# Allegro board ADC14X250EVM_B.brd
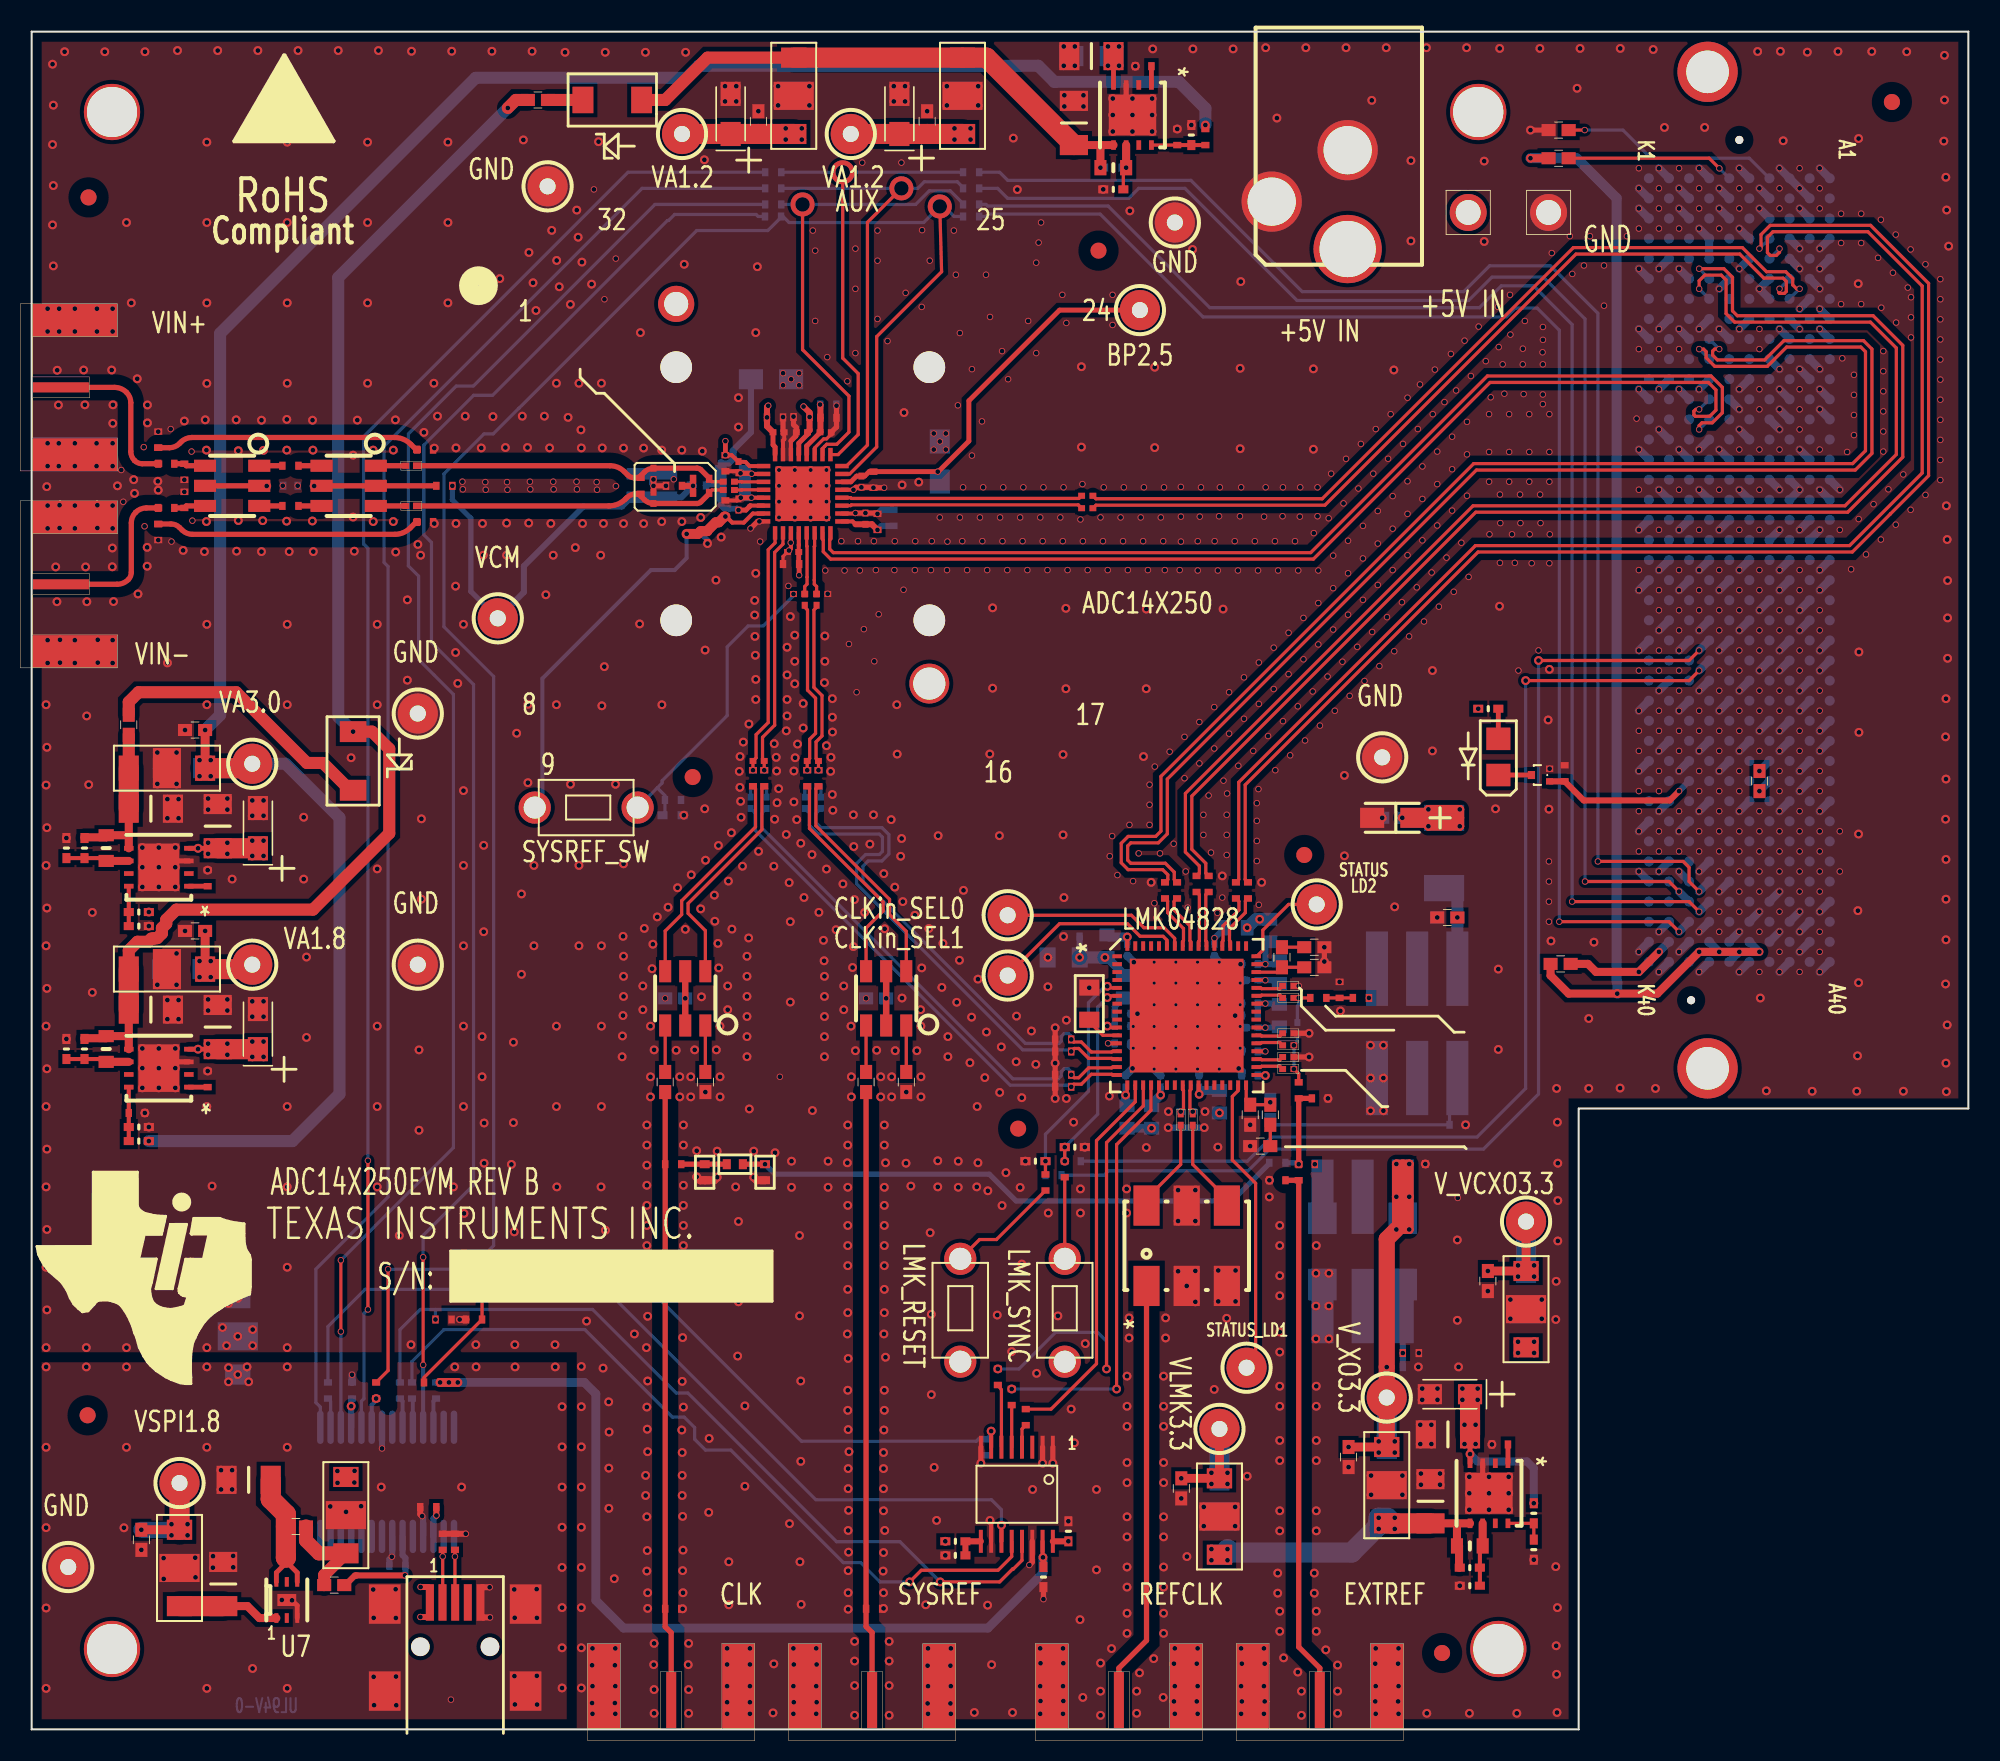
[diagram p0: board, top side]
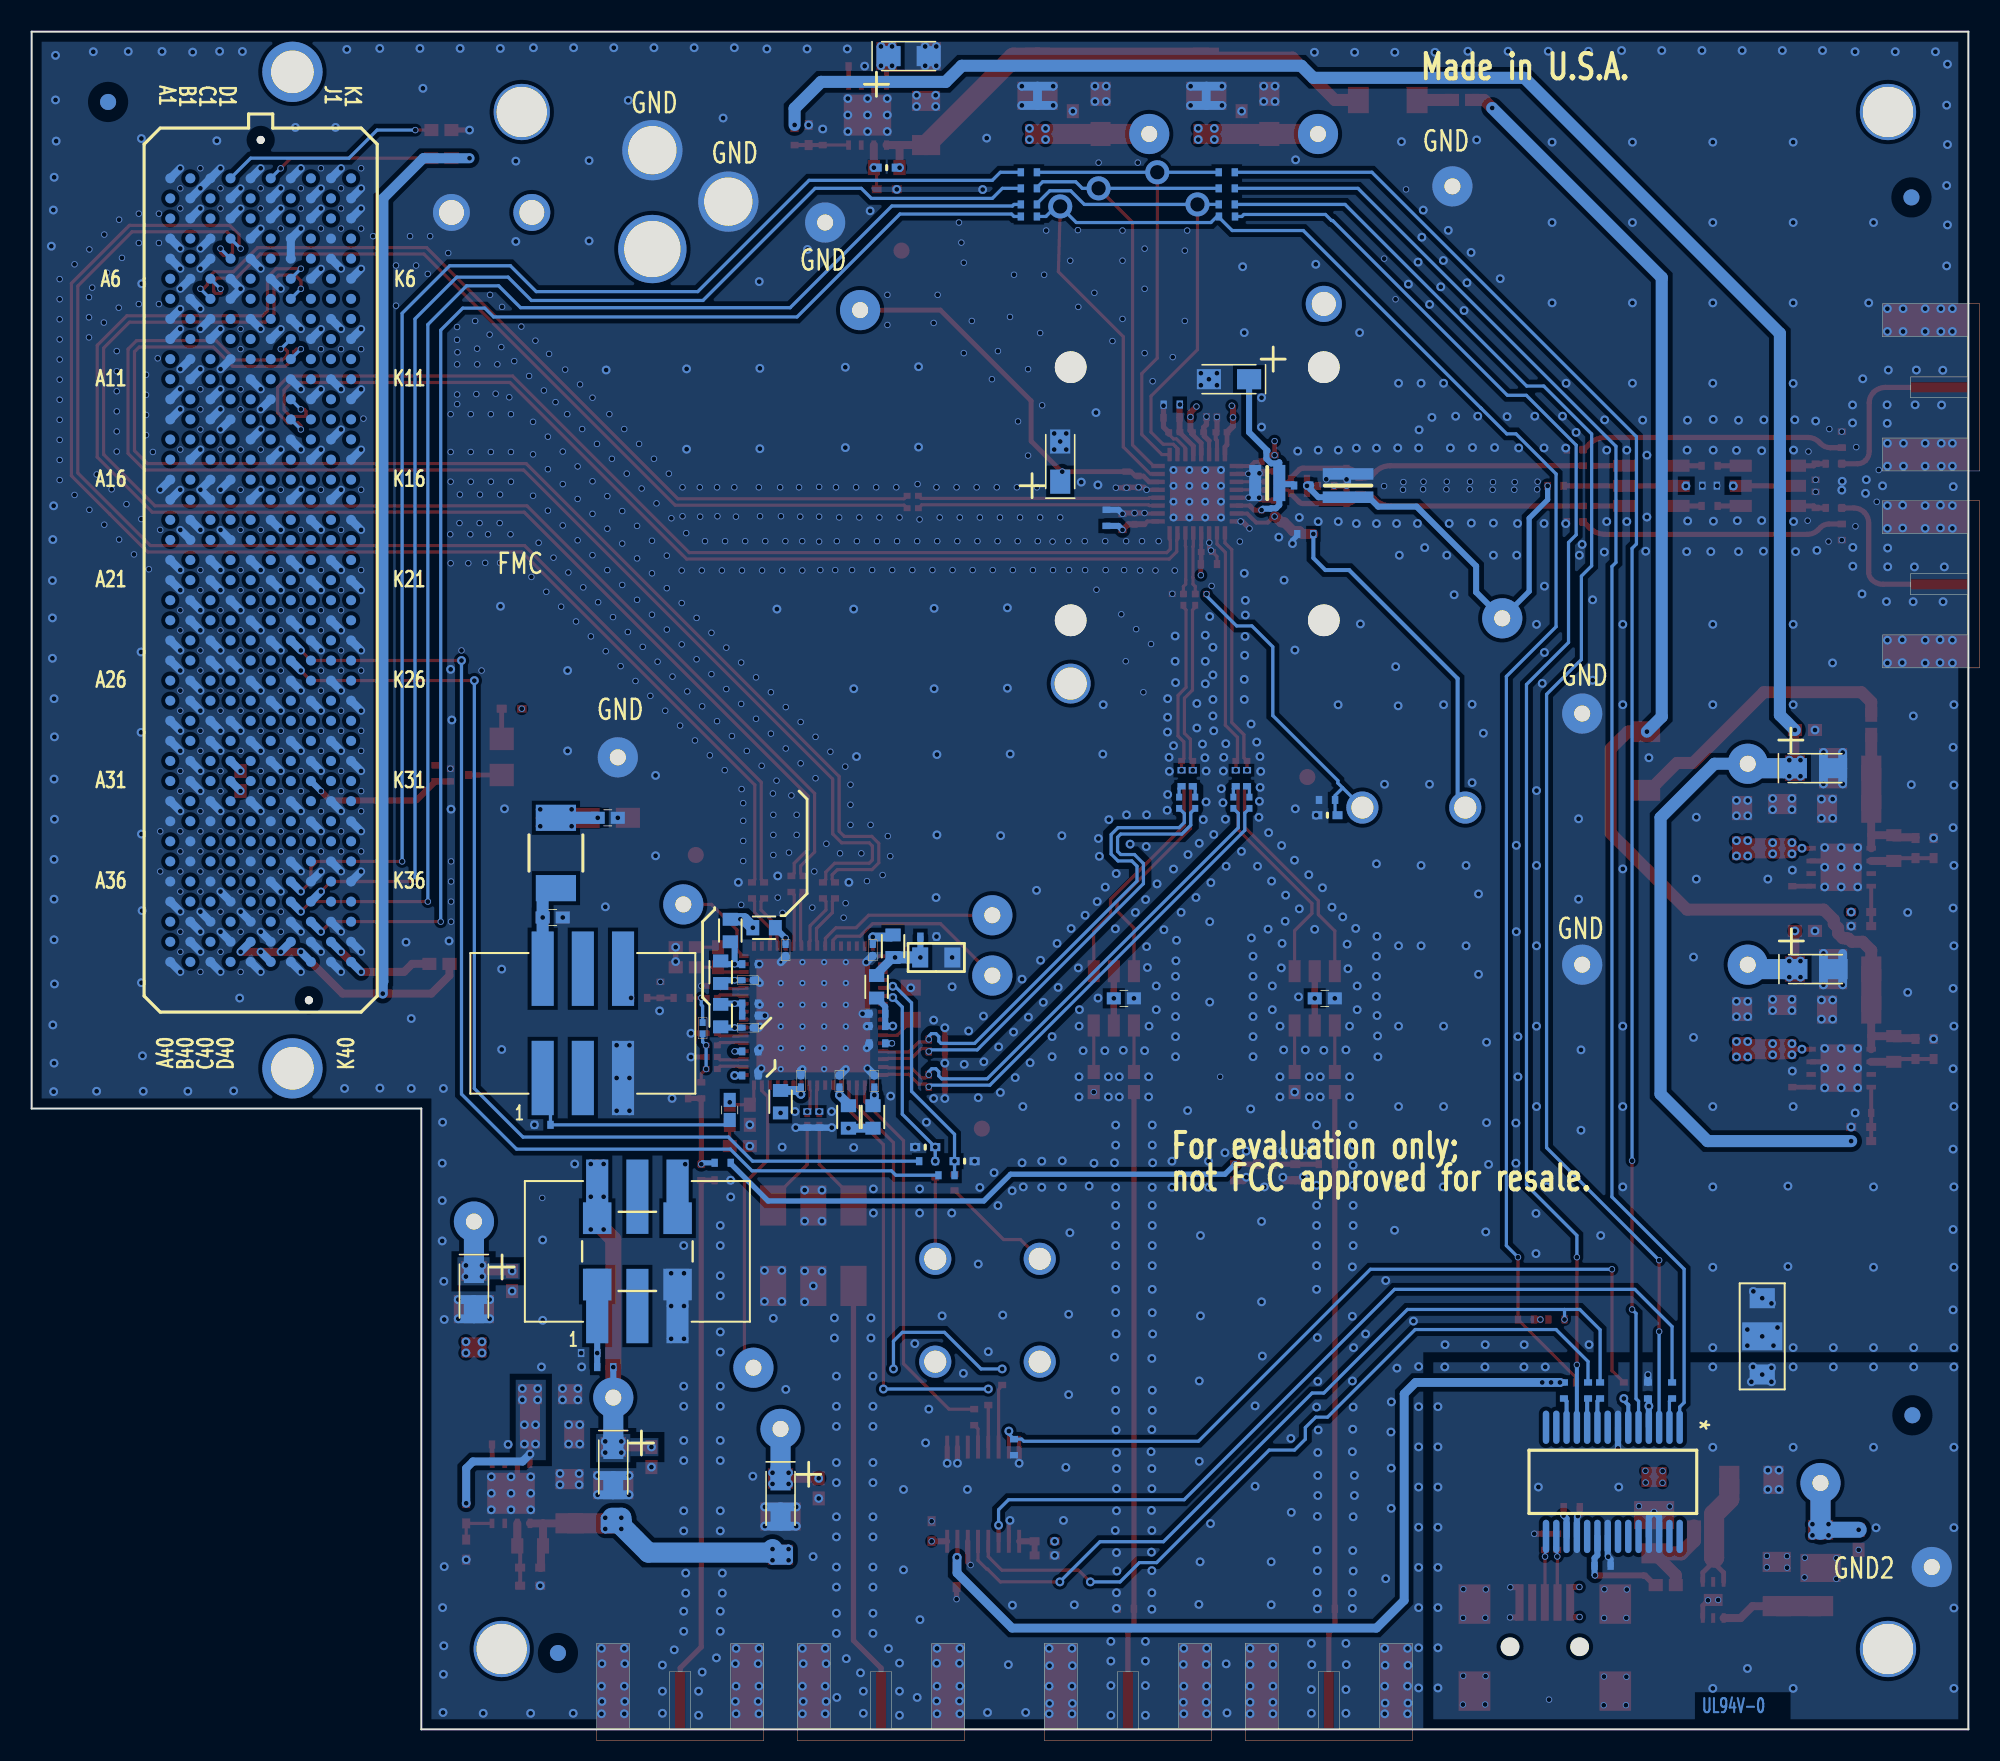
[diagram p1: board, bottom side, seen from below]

Outline 122.42 x 107.31 mm; copper layers: TOP, L2_GND, L3_POWER, L4_GND, L5_GND, BOTTOM. Coordinates in mm from the lower left corner of the outline.
Outline path: 0,107.31 0,0 97.79,0 97.79,39.24 122.42,39.24 122.42,107.31 0,107.31

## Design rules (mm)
net group CLKIN: nets CLKIN+ CLKIN-
net group CLKOUT2: nets CLKOUT2+ CLKOUT2-
net group CLKOUT3: nets CLKOUT3+ CLKOUT3-
net group CLKOUT4: nets CLKOUT4+ CLKOUT4-
net group CLKOUT8: nets CLKOUT8+ CLKOUT8-
net group CLKOUT10: nets CLKOUT10+ CLKOUT10-
net group CLKOUT11: nets CLKOUT11+ CLKOUT11-
net group DIFFPAIR3: nets SYNCB+ SYNCB-
net group DIFFPAIR5: nets N17242573 N17242594
net group DIFFPAIR6: nets SO+ SO-
net group EXT_CLK: nets EXT_CLK+ EXT_CLK-
net group EXT_SYSREF: nets EXT_SYSREF+ EXT_SYSREF-
net group FMC_FPGA_DEVCLKA: nets FMC_FPGA_DEVCLKA+ FMC_FPGA_DEVCLKA-
net group FMC_FPGA_DEVCLKB: nets FMC_FPGA_DEVCLKB+ FMC_FPGA_DEVCLKB-
net group FMC_FPGA_SYSREF: nets FMC_FPGA_SYSREF+ FMC_FPGA_SYSREF-
net group LMK_ADC_DEVCLK: nets LMK_ADC_DEVCLK+ LMK_ADC_DEVCLK-
net group LMK_ADC_SYSREF: nets LMK_ADC_SYSREF+ LMK_ADC_SYSREF-
net group REFCLK: nets REFCLK+ REFCLK-
net group SSREF: nets SSYSREF+ SSYSREF-
net group SYSREF: nets SYSREF+ SYSREF-
net group VIN: nets VIN+ VIN-

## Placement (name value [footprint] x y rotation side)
C1  0.1u  [C0402_NO_SS]  43.85 80.04 270 top
C2  0.01u  [0201]  44.68 79.78 270 top
C3  10u  [C0402_NO_SS]  41.91 75.56 180 bottom
C4  10u  [C0402_NO_SS]  54.48 76.58 270 bottom
C5  10u  [C0402_NO_SS]  50.36 83.74 180 bottom
C7  0.1u  [C0402_NO_SS]  46.99 82.93 0 top
C8  0.01u  [0201]  47.22 81.99 0 top
C9  0.1u  [C0402_NO_SS]  50.37 82.91 0 top
C10  0.01u  [0201]  50.19 81.99 0 top
C11  0.1u  [C0402_NO_SS]  43.85 77.17 90 top
C12  0.01u  [0201]  42.71 75.39 270 top
C13  0.01u  [0201]  48.69 81.99 180 top
C14  A/R  [C0402_NO_SS]  17.32 78.61 180 bottom
C15  0.1u  [C0402_NO_SS]  48.67 82.96 180 top
C16  A/R  [C0402_NO_SS]  15.39 78.61 0 bottom
C17  A/R  [0201]  39.31 79.37 270 top
C18  0.1u  [C0402_NO_SS]  48.01 73.66 180 top
C19  A/R  [C0402_NO_SS]  38.49 78.61 270 top
C20  0.01u  [C0402_NO_SS]  16.36 79.88 0 top
C21  0.01u  [C0402_NO_SS]  16.36 77.34 0 top
C22  1u  [C0402_NO_SS]  40.6 78.61 180 top
C23  A/R  [0201]  39.31 77.84 90 top
C24  0.01u  [0201]  48.13 74.42 180 top
C25  0.1u  [0201]  44.68 77.43 90 top
C26  1u  [0508]  44.32 78.78 0 bottom
C27  10u  [CAP_A-CASE]  46.74 85.34 0 bottom
C28  0.1u  [0603]  40.05 40.92 90 top
C29  0.1u  [0603]  42.59 40.92 90 top
C31  0.1u  [0603]  40.68 46.21 180 bottom
C32  10u  [0612]  39.21 78.62 90 bottom
C34  0.1u  [C0402_NO_SS]  53.47 76.33 90 top
C35  0.01u  [0201]  52.7 76.53 90 top
C36  0.01u  [0201]  66.73 77.98 0 top
C37  0.01u  [0201]  66.73 77.19 0 top
C43  0.01u  [0201]  52.45 78.87 270 top
C44  0.1u  [C0402_NO_SS]  53.21 78.99 270 top
C45  10u  [CAP_A-CASE]  57.4 80.14 90 bottom
C47  0.1u  [C0402_NO_SS]  68.97 43.36 0 bottom
C48  10u  [0805]  66.85 45.87 90 top
C51  0.1u  [C0402_NO_SS]  81.33 46.23 0 top
C53  0.1u  [0603]  52.75 40.92 90 top
C55  0.1u  [0603]  55.29 40.92 90 top
C56  0.1u  [0603]  53.38 46.21 180 bottom
C57  A/R  [C0402_NO_SS]  87.18 23.79 0 bottom
C58  A/R  [C0402_NO_SS]  87.59 35.74 0 top
C59  0.1u  [0603]  86 57.62 180 bottom
C60  10u  [SMD_SIZE3216]  86 57.62 180 top
C61  0.1u  [C0402_NO_SS]  68.97 44.46 0 bottom
C63  A/R  [C0402_NO_SS]  90.13 38.21 0 bottom
C64  100p  [0603]  89.48 51.32 180 bottom
C65  0.1u  [0603]  89.48 51.32 180 top
C66  0.1u  [0201]  79.43 47 180 top
C67  A/R  [0201]  79.43 46.23 180 top
C68  0.1u  [0201]  48.87 58.57 90 bottom
C69  0.1u  [0201]  49.89 58.57 90 bottom
C70  0.1u  [0201]  45.44 58.57 90 bottom
C71  0.1u  [0201]  46.46 58.57 90 bottom
C80  0.1u  [0201]  73.39 38.54 270 top
C81  0.1u  [0201]  72.63 38.54 270 top
C82  0.1u  [SMD_SIZE0402]  65.53 12.52 270 top
C83  0.1u  [SMD_SIZE0402]  63.96 9.63 90 top
C84  0.1u  [C0402_NO_SS]  25.07 14.05 180 top
C86  47p  [C0402_NO_SS]  26.76 11.85 90 top
C87  0.1u  [SMD_SIZE0402]  40.51 57.78 180 bottom
C92  10u  [0805]  65.24 48.79 180 bottom
C93  1u  [C0402_NO_SS]  65.74 50.11 180 bottom
C95  0.1u  [0603]  6.93 11.98 270 top
C96  10u  [SMD_SIZE1206]  13.72 15.77 180 top
C99  0.1u  [0603]  45.94 101.65 90 top
C102  10u  [SMD_SIZE1206]  12.11 9.19 90 top
C103  10u  [CAP_A-CASE]  66.99 105.77 180 bottom
C104  10u  [CAP_A-CASE]  44.18 102.12 90 top
C105  1u  [SMD_SIZE1206]  66.99 105.77 180 top
C106  0.1u  [C0402_NO_SS]  72.42 100.65 270 top
C107  2.2n  [SMD_SIZE0603]  68.37 98.72 0 top
C108  0.01u  [C0402_NO_SS]  70.27 105.13 180 top
C109  10u  [SMD_SIZE1206]  65.88 101.54 90 top
C110  0.1u  [SMD_SIZE0402]  63.45 35.92 0 top
C111  0.1u  [0603]  56.61 101.65 90 top
C112  10u  [CAP_A-CASE]  54.85 102.12 90 top
C113  0.1u  [0603]  10.33 50.47 180 top
C114  10u  [CAP_A-CASE]  14.3 44.26 90 top
C115  10u  [CAP_A-CASE]  9.66 48.06 180 bottom
C116  1u  [SMD_SIZE1206]  11.76 44.39 90 top
C117  0.1u  [SMD_SIZE0402]  65.94 36.8 180 bottom
C118  1u  [C0402_NO_SS]  68.97 45.24 0 bottom
C119  0.1u  [C0402_NO_SS]  6.65 38.96 180 top
C120  2.2n  [SMD_SIZE0603]  4.71 43.01 270 top
C121  0.01u  [C0402_NO_SS]  11.13 41.1 90 top
C122  10u  [SMD_SIZE1206]  7.54 45.5 0 top
C123  0.1u  [0603]  10.33 63.17 180 top
C125  10u  [CAP_A-CASE]  14.3 56.96 90 top
C126  47uF  [CAP_A-CASE]  9.7 60.76 180 bottom
C127  1u  [SMD_SIZE1206]  11.76 57.09 90 top
C128  0.1u  [0603]  72.67 15.23 270 top
C129  2.2n  [SMD_SIZE0603]  4.71 55.71 270 top
C131  0.01u  [C0402_NO_SS]  11.13 53.8 90 top
C132  10u  [SMD_SIZE1206]  7.54 58.2 0 top
C133  10u  [CAP_A-CASE]  75.08 14.6 270 bottom
C134  0.1u  [0603]  83.24 17.21 270 top
C136  10u  [CAP_A-CASE]  85.66 16.58 270 bottom
C137  10u  [CAP_A-CASE]  89.65 21.19 180 top
C139  1u  [SMD_SIZE1206]  89.52 18.65 180 top
C140  0.1u  [0603]  92.05 28.34 270 top
C141  1u  [C0402_NO_SS]  77 45.12 180 bottom
C142  2.2n  [SMD_SIZE0603]  90.91 11.6 0 top
C144  0.01u  [C0402_NO_SS]  92.81 18.01 180 top
C145  10u  [SMD_SIZE1206]  88.42 14.42 90 top
C146  10u  [CAP_A-CASE]  94.46 27.7 270 bottom
C152  0.1u  [0201]  69.15 40.97 90 bottom
C158  47p  [C0402_NO_SS]  25.98 11.85 90 top
C159  0.1u  [C0402_NO_SS]  80.09 40.39 90 top
C160  0.1u  [C0402_NO_SS]  77 41.33 180 bottom
C161  0.01u  [C0402_NO_SS]  23.12 10.34 180 bottom
C162  0.01u  [C0402_NO_SS]  20.25 21.42 90 bottom
C164  0.1u  [C0402_NO_SS]  77 48.37 180 bottom
C179  A/R  [0201]  49.97 71.77 0 top
C186  0.1u  [0201]  48.87 71.41 270 top
C187  0.1u  [0201]  49.62 71.41 270 top
C195  0.1u  [0201]  79.43 42.5 180 top
C196  0.1u  [0201]  79.43 41.74 180 top
C197  0.1u  [0201]  79.43 44 180 top
C198  A/R  [0201]  79.43 43.24 180 top
C199  0.1u  [C0402_NO_SS]  77 42.86 180 bottom
C200  0.1u  [0201]  71.36 40.97 90 bottom
C201  0.1u  [0201]  73.8 40.97 90 bottom
C202  0.1u  [0201]  74.76 49.25 270 bottom
C203  0.1u  [0201]  69.25 49.25 270 bottom
C204  0.1u  [C0402_NO_SS]  77 45.88 180 bottom
C205  0.1u  [0201]  77.15 47.35 180 bottom
C206  0.1u  [0201]  77.15 44.36 180 bottom
D1  DIODE,SCHOTTKY,CDBA140-G  [ZENER_DO_214AC]  20.32 61.21 90 top
D2  DIODE,SCHOTTKY,CDBA140-G  [ZENER_DO_214AC]  36.7 103 0 top
J1  CONN, JACK, PWR  [CON_RAPC722_JACK_THVT_3]  83.19 96.7 180 top
J2  CONN, SMA, JACK, 50 OHM, EDGE  [CON_SMA-EDGE]  1.84 84.83 0 top
J3  CONN, SMA, JACK, 50 OHM, EDGE  [CON_SMA-EDGE]  1.84 72.38 0 top
J4  CONN, SMA, JACK, 50 OHM, EDGE  [CON_SMA-EDGE]  40.43 1.84 90 top
J5  CONN, SMA, JACK, 50 OHM, EDGE  [CON_SMA-EDGE]  53.13 1.84 90 top
J6  CONN, SMA, JACK, 50 OHM, EDGE  [CON_SMA-EDGE]  68.73 1.84 90 top
J7  CONN, SMA, JACK, 50 OHM, EDGE  [CON_SMA-EDGE]  81.43 1.84 90 top
J8  CON, SMVT, HS, FIELD ARRAY, FMC, MALE  [CON_SMVT_40X10_SEAM_MTG]  107.94 73.28 90 bottom
J9  CONN, USB, MINI AB, R/A, SMT  [CON_SMRT_USBMNE20_F]  26.77 4.57 90 top
L3  330 OHM  [R0603]  69.01 46.94 90 bottom
L4  330 OHM  [R0603]  69.24 38.71 90 bottom
L5  330 OHM  [R0603]  78.26 50.5 90 bottom
L8  100uH, 158MA, 8 OHM  [SMD_SIZE1812R]  89.28 55.4 270 bottom
L9  330 OHM  [R0603]  70.79 38.71 90 bottom
L10  330 OHM  [R0603]  75.08 39.67 90 bottom
L11  330 OHM  [R0603]  76.12 50.67 180 bottom
L12  330 OHM  [R0603]  67.97 49.5 90 bottom
L13  330 OHM  [R0603]  78.87 45.12 270 bottom
L14  330 OHM  [R0603]  78.87 47.86 270 bottom
LF1_C1  8200p  [0603]  77.02 38.85 270 top
LF1_C2  0.39u  [0603]  78.29 38.85 270 top
LF1_R2  3.30k  [0603]  77.66 36.87 180 top
LF2_C1  27p  [0603]  81.08 48.17 0 top
LF2_C2  2700p  [0603]  79.03 48.81 90 top
LF2_R2  560  [0603]  81.08 49.44 0 top
MT1  STANDOFF, FEMALE, 4-40 X 1 1/16"  [MFG125_PLATED]  5.08 5.08 0 top
MT2  STANDOFF, FEMALE, 4-40 X 1 1/16"  [MFG125_PLATED]  92.71 5.08 0 top
MT3  STANDOFF, FEMALE, 4-40 X 1 1/16"  [MFG125_PLATED]  5.08 102.23 0 top
MT4  STANDOFF, FEMALE, 4-40 X 1 1/16"  [MFG125_PLATED]  91.44 102.23 0 top
NOREF  -  []  37.85 -41.53 0 top
NOREF#2  -  []  19.5 27.7 0 top
NOREF#3  -  []  2.79 25.7 0 top
NOREF#4  -  [unnamed#2]  67.44 93.47 0 top
NOREF#5  -  []  5.08 5.08 0 top
NOREF#6  -  [unnamed#2]  62.36 37.97 0 top
NOREF#7  -  [unnamed#2]  3.54 19.85 0 top
NOREF#8  -  []  -39.24 41.53 0 top
NOREF#9  -  []  0 0 90 top
NOREF#10  -  []  111.07 13.72 0 top
NOREF#11  -  []  5.08 5.08 90 top
NOREF#12  -  []  0 107.31 0 top
NOREF#13  -  [unnamed#2]  41.78 60.2 0 top
NOREF#14  -  []  0 0 0 top
NOREF#15  -  [unnamed#2]  117.59 102.87 0 top
NOREF#16  -  [unnamed#2]  3.6 96.84 0 top
NOREF#17  -  []  15.87 95.52 0 top
NOREF#18  -  [unnamed#2]  89.15 4.83 0 top
NOREF#19  -  []  205.23 22.35 0 top
NOREF#20  -  []  5.08 5.08 0 top
NOREF#21  -  [unnamed#2]  80.44 55.27 0 top
NOREF#22  -  []  15.91 102.61 0 top
NOREF#23  -  []  0 0 90 top
NOREF#24  -  []  35.64 39.22 180 bottom
NOREF#25  -  [unnamed#2]  3.6 96.84 180 bottom
NOREF#26  -  [unnamed#2]  117.59 102.87 180 bottom
NOREF#27  -  []  50.52 36.17 180 bottom
NOREF#28  -  [unnamed#2]  89.15 4.83 180 bottom
NOREF#29  -  [unnamed#2]  3.54 19.85 180 bottom
Q1  SSM3K37MFV,L3F  [SOT-723]  95.38 60.33 90 top
R1  0  [C0402_NO_SS]  8 81.52 90 top
R2  0  [C0402_NO_SS]  8 75.68 270 top
R3  0  [0201]  24 79.88 0 top
R4  A/R  [C0402_NO_SS]  9.65 77.72 270 top
R5  A/R  [C0402_NO_SS]  8 76.7 270 top
R6  A/R  [C0402_NO_SS]  24.36 76.83 90 top
R7  33  [C0402_NO_SS]  42.32 79.05 180 top
R8  A/R  [C0402_NO_SS]  26.09 78.61 0 top
R9  33  [C0402_NO_SS]  42.32 78.16 180 top
R10  0  [0201]  24 77.34 0 top
R11  A/R  [C0402_NO_SS]  8.51 80 0 top
R12  A/R  [C0402_NO_SS]  8 80.51 90 top
R13  A/R  [C0402_NO_SS]  24.36 80.38 270 top
R14  0  [C0402_NO_SS]  9.65 79.49 270 top
R15  0  [C0402_NO_SS]  8.51 77.21 0 top
R16  10  [C0402_NO_SS]  42.11 78.63 0 bottom
R17  75  [0402]  44.45 35.73 0 top
R18  A/R  [0201]  45.95 61.21 180 top
R19  300  [0402]  42.55 35.22 270 top
R20  300  [0402]  46.35 35.22 270 top
R21  0  [C0402_NO_SS]  40.55 35.73 180 top
R22  100  [C0402_NO_SS]  40.55 7.62 0 top
R23  100  [C0402_NO_SS]  53.25 7.62 0 top
R24  0  [0201]  44.07 78.87 0 top
R25  0  [0201]  44.07 78.34 0 top
R27  10K  [C0402_NO_SS]  60.32 17.84 90 bottom
R28  56  [SMD_SIZE0402]  92.08 64.52 0 top
R29  100  [0201]  49.38 61.21 180 top
R30  0  [0201]  80.01 44.32 270 bottom
R31  A/R  [C0402_NO_SS]  86.16 22.9 180 bottom
R32  A/R  [C0402_NO_SS]  87.18 23.79 180 top
R33  A/R  [C0402_NO_SS]  80.6 35.73 0 top
R34  200  [C0402_NO_SS]  80.09 35.22 90 top
R35  49.9  [C0402_NO_SS]  78.75 34.71 0 top
R36  200  [C0402_NO_SS]  81.43 39.88 180 top
R37  0  [0603]  78.29 39.15 270 bottom
R38  200  [C0402_NO_SS]  84.02 46.23 0 top
R39  200  [C0402_NO_SS]  82.68 46.74 270 top
R40  0  [C0402_NO_SS]  45.6 60.12 90 top
R41  0  [C0402_NO_SS]  46.31 60.12 90 top
R42  0  [0603]  96.65 48.39 0 top
R43  A/R  [C0402_NO_SS]  45.6 60.12 90 bottom
R44  0  [C0402_NO_SS]  49.02 60.12 90 top
R45  0  [C0402_NO_SS]  49.74 60.12 90 top
R46  121  [C0402_NO_SS]  65.2 42.85 0 top
R47  121  [C0402_NO_SS]  65.2 43.61 0 top
R48  121  [C0402_NO_SS]  65.2 40.62 0 top
R49  121  [C0402_NO_SS]  65.2 41.38 0 top
R50  A/R  [C0402_NO_SS]  46.31 60.12 90 bottom
R51  A/R  [C0402_NO_SS]  49.02 60.12 90 bottom
R52  0  [C0402_NO_SS]  24.87 80.89 0 top
R53  0  [C0402_NO_SS]  24.87 76.32 0 top
R54  121  [C0402_NO_SS]  73.39 38.54 90 bottom
R55  121  [C0402_NO_SS]  72.63 38.54 90 bottom
R56  2  [0603]  6.14 63.5 270 top
R57  22  [C0402_NO_SS]  62.84 19.74 90 top
R58  22  [C0402_NO_SS]  61.07 22.28 90 top
R59  22  [C0402_NO_SS]  61.95 21.01 90 top
R60  10K  [C0402_NO_SS]  25.56 21.42 90 bottom
R61  A/R  [C0402_NO_SS]  49.74 60.12 90 bottom
R62  2  [0603]  32 103 180 top
R63  1K  [SMD_SIZE0402]  68.37 97.35 180 top
R64  200  [SMD_SIZE0402]  68.37 98.72 180 bottom
R65  20K  [C0402_NO_SS]  74.19 100.65 90 top
R66  1K  [SMD_SIZE0402]  2.2 43.01 90 top
R67  806  [SMD_SIZE0402]  3.34 43.01 90 top
R68  10K  [SMD_SIZE0402]  6.77 37.19 180 top
R69  1K  [SMD_SIZE0402]  2.2 55.71 90 top
R70  22  [C0402_NO_SS]  46.88 97.41 0 bottom
R71  22  [C0402_NO_SS]  18.73 21.42 90 bottom
R72  22  [C0402_NO_SS]  46.88 96.39 0 bottom
R73  22  [C0402_NO_SS]  46.88 98.42 0 bottom
R74  22  [C0402_NO_SS]  21.78 21.42 90 top
R75  22  [C0402_NO_SS]  23.28 21.42 90 bottom
R76  22  [C0402_NO_SS]  24.04 21.42 90 bottom
R77  22  [C0402_NO_SS]  46.86 95.63 0 bottom
R78  2k  [SMD_SIZE0402]  3.34 55.71 90 top
R79  1K  [SMD_SIZE0402]  90.91 9.08 180 top
R80  2.32K  [SMD_SIZE0402]  90.91 10.22 180 top
R81  1K  [SMD_SIZE0402]  94.95 13.66 270 top
R82  A/R  [SMD_SIZE0402]  94.95 11.36 270 top
R83  10K  [C0402_NO_SS]  27.96 25.91 180 top
R84  10K  [C0402_NO_SS]  26.04 25.91 0 top
R85  A/R  [C0402_NO_SS]  25.31 21.93 0 top
R86  0  [SMD_SIZE0402]  58.39 11.89 0 top
R87  0  [SMD_SIZE0402]  58.39 11 0 top
R89  A/R  [SMD_SIZE0402]  73.3 100.78 270 top
R90  A/R  [SMD_SIZE0402]  6.77 38.07 180 top
R92  A/R  [C0402_NO_SS]  59.39 97.41 180 bottom
R93  A/R  [C0402_NO_SS]  59.39 98.42 0 bottom
R94  A/R  [C0402_NO_SS]  59.39 96.39 0 bottom
R95  A/R  [C0402_NO_SS]  59.39 95.63 180 bottom
R96  1K  [SMD_SIZE0402]  6.77 51.66 180 top
R97  A/R  [SMD_SIZE0402]  6.77 50.77 0 top
R102  10K  [C0402_NO_SS]  96.9 60.43 270 top
R110  1K  [SMD_SIZE0402]  63.45 35.92 180 bottom
R111  1K  [SMD_SIZE0402]  65.94 36.8 0 top
R112  0  [C0402_NO_SS]  64.08 34.57 90 top
R113  0  [C0402_NO_SS]  64.59 35.03 180 bottom
R114  0  [C0402_NO_SS]  65.81 35.92 180 bottom
R115  0  [C0402_NO_SS]  65.3 35.41 90 top
R116  0  [0603]  109.22 59.94 270 top
R119  A/R  [0201]  48.51 71.77 180 top
R120  10K  [C0402_NO_SS]  40.54 58.75 0 bottom
R155  10K  [0603]  96.52 101.09 180 top
R156  10K  [0603]  96.52 99.31 0 top
R157  0  [0603]  16.71 12.82 180 top
R158  0  [0603]  19.13 9.12 0 top
R160  0  [C0402_NO_SS]  71.64 53.03 90 top
R161  0  [C0402_NO_SS]  72.4 53.03 90 top
R162  0  [C0402_NO_SS]  73.63 53.44 90 top
R163  0  [C0402_NO_SS]  74.4 53.44 90 top
R164  0  [C0402_NO_SS]  76.12 53.03 90 top
R165  0  [C0402_NO_SS]  76.89 53.03 90 top
R227  0  [C0402_NO_SS]  78.74 35.81 180 bottom
SW1  SW, PUSHBUTTON, SPST-NO  [SW_RESET_PTS635]  65.3 26.49 90 top
SW2  SW, PUSHBUTTON, SPST-NO  [SW_RESET_PTS635]  58.7 26.49 90 top
SW3  SW, PUSHBUTTON, SPST-NO  [SW_RESET_PTS635]  35.05 58.27 0 top
SYNC  LED GREEN  [LED_0805]  92.71 61.47 270 top
T1  -  [MABA-007159-000000]  12.67 78.61 270 top
T2  -  [MABA-007159-000000]  20.04 78.61 270 top
T3  -  [MABA-007159-000000]  41.32 46.21 180 top
T4  -  [MABA-007159-000000]  54.02 46.21 180 top
T5  ADT2-1T-1P+  [ADT1-1WT]  73.01 30.57 90 top
TP1  BLK  [TP_THVT_100_RND_GND]  72.26 95.25 0 top
TP2  RED  [TP_THVT_100_RND]  41.11 100.85 0 top
TP3  RED  [TP_THVT_100_RND]  51.78 100.85 0 top
TP4  RED  [TP_THVT_100_RND]  13.94 48.34 0 top
TP5  RED  [TP_THVT_100_RND]  13.94 61.04 0 top
TP6  RED  [TP_THVT_100_RND]  75.08 18.99 0 top
TP7  RED  [TP_THVT_100_RND]  85.66 20.97 0 top
TP8  RED  [TP_THVT_100_RND]  94.46 32.1 0 top
TP9  BLK  [TP_THVT_100_RND_GND]  85.37 61.44 0 top
TP10  BLK  [TP_THVT_100_RND_GND]  32.61 97.54 0 top
TP11  BLK  [TP_THVT_100_RND_GND]  24.41 48.34 0 top
TP12  BLK  [TP_THVT_100_RND_GND]  24.41 64.21 0 top
TP13  BLK  [TP_THVT_100_RND_GND]  2.31 10.26 0 top
TP14  WHT  [TP_THVT_100_RND]  70.05 89.71 0 top
TP15  WHT  [TP_THVT_100_RND]  29.46 70.23 0 top
TP16  GRN  [TP_THVT_100_RND]  61.7 47.65 0 top
TP17  GRN  [TP_THVT_100_RND]  61.7 51.46 0 top
TP18  GRN  [TP_THVT_100_RND]  81.23 52.15 0 top
TP19  GRN  [TP_THVT_100_RND]  76.8 22.86 0 top
TP20  RED  [TP_THVT_100_RND]  9.35 15.57 0 top
TP21  Testloop_Red  [TESTPOINT_62DIA]  90.81 95.89 0 top
TP22  Testloop_Black  [TESTPOINT_62DIA]  95.89 95.89 0 top
U1  ADC14X250  [QFN_32_IRONWOOD_0P5MM]  48.74 78.11 0 top
U5  SN74AVC4T774  [TSSOP16_PW]  62.28 14.86 270 top
U6  -  [FT245RL]  22.47 15.65 270 bottom
U7  LP5900SD-1.8/NOPB  [SC-MKT-SDB06A_6LLP]  16.13 8.18 90 top
U8  LP3878SD-ADJ  [SC-MKT-SDC08A_LLP]  69.58 102.04 270 top
U9  LP3878SD-ADJ  [SC-MKT-SDC08A_LLP]  8.04 41.8 180 top
U10  LP3878SD-ADJ  [SC-MKT-SDC08A_LLP]  8.04 54.5 180 top
U11  LP3878SD-ADJ  [SC-MKT-SDC08A_LLP]  92.12 14.92 270 top
U13  LMK04828BISQ  [WQFN_64_360X360_0P5MM_PWRPAD]  73.01 45.12 0 top
Y1  CCHD-950-61.44  [SOIC6_100_WG272_L560]  84.13 30.21 90 bottom
Y2  CWX823-012.288M  [CWX813]  84.13 30.21 90 bottom
Y3  CVHD-950-122.88  [SOIC6_100_WG272_L560]  87.58 44.63 90 bottom
Z1  0.2uF, 2A,NFM41P  [NFM41P]  19.86 13.54 270 top
Z2  0.2uF, 2A,NFM41P  [NFM41P]  13.03 24.84 90 bottom
Z3  0.2uF, 2A,NFM41P  [NFM41P]  9.35 10.2 90 top
Z4  0.2uF, 2A,NFM41P  [NFM41P]  48.17 103.26 270 top
Z5  0.2uF, 2A,NFM41P  [NFM41P]  58.84 103.26 270 top
Z6  0.2uF, 2A,NFM41P  [NFM41P]  8.55 48.06 0 top
Z7  0.2uF, 2A,NFM41P  [NFM41P]  8.55 60.76 0 top
Z8  0.2uF, 2A,NFM41P  [NFM41P]  75.08 13.45 90 top
Z9  0.2uF, 2A,NFM41P  [NFM41P]  85.66 15.44 90 top
Z10  0.2uF, 2A,NFM41P  [NFM41P]  94.46 26.56 90 top

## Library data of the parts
C1 C2 C7-C15 C18 C20 C21 C24 C34 C35 C43 C44 C47 C48 C51 C57 C61 C63 C84 C86 C92 C106 C108 C119 C121 C131 C144 C158-C162 C164 C199 C204 = Cap_0
C3-C5 C22 C32 C93 C118 C141 = CAPACITOR NON-POL
C16 C17 C19 C23 C25 C26 C31 C56 C58 C59 C64 C65 C82 C83 C95 C96 C99 C102 C105 C109 C111 C113 C116 C122 C123 C127 C128 C132 C134 C139 C140 C145 LF1_C1 LF1_C2 LF2_C1 LF2_C2 = Capacitor_0
C27 C45 C60 C103 C104 C112 C114 C115 C125 C126 C133 C136 C137 C146 = Cap_Polar_1
C28 C29 C53 C55 = CAP_0603_0.1uF_H
C36 C37 C66-C71 C80 C81 C152 C179 C186 C187 C195-C198 C200-C203 C205 C206 = CAP_0201_0.1uF
C87 C107 C110 C117 C120 C129 C142 = Capacitor_1
D1 D2 = DIODE_SCHOTTKY
J1 = CONN JACK PWR
J2-J7 = SMA_CONN_0
J8 = CON_SMVT_40X10_SEAM
J9 = USB_MINI_AB_MNE20-5G5P10
L3-L5 L9-L14 = INDUCTOR FERRITE/SM
L8 = Inductor_0
LF1_R2 LF2_R2 R1 R2 R4-R9 R11-R16 R18 R21-R23 R27 R29 R31-R55 R57-R61 R63-R87 R89 R90 R92-R97 R102 R110-R116 R119 R120 R157 R158 R160-R165 R227 = Resistor_0
MT1-MT4 = MOUNTING_HOLE
Q1 = BSS138/SOT
R3 R10 R24 R25 = Res_0201_Zero_H
R17 = Res_0402_75
R19 R20 = Res_0402_300
R28 = Res_0402_56
R30 = Res_0402_Zero_DNI
R56 R62 = Res_0603_22.1
R155 R156 = Res_0603_10k_H
SW1-SW3 = SW PUSHBUTTON
SYNC = LED
T1-T4 = MABA-007159-000000
T5 = ADT2-1T-1P+_0
TP1 TP9-TP13 = TESTPOINT_BLK
TP2-TP8 TP20 = TESTPOINT_RED
TP14 TP15 = TESTPOINT_WHT
TP16-TP19 = TESTPOINT_GRN
TP21 TP22 = TESTLOOP_BLACK
U1 = ADC14X250_SOCKET_0
U5 = SN74AVC4T774
U6 = FT245RL
U7 = LP5900SD-??_1
U8-U11 = LP3878MR-ADJ_1
U13 = LMK04828BISQ
Y1 = CCHD-950-61.44
Y2 = CWX823-012.288M
Y3 = CVHD-950-122.88
Z1-Z10 = NFM41_0

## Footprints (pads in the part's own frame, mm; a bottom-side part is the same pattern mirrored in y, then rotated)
0201
  rect 0.432x0.381 smd: 1(-0.356,0) 2(0.356,0)
0402
  rect 0.508x0.635 smd: 1(-0.508,0) 2(0.508,0)
0508
  rect 0.762x2.286 smd: 1(-0.762,0) 2(0.762,0)
0603
  rect 0.889x0.762 smd: 1(-0.635,0) 2(0.635,0)
0612
  rect 0.725x3.2 smd: 1(-0.738,0) 2(0.738,0)
0805
  rect 1.016x1.27 smd: 1(-1.016,0) 2(1.016,0)
ADT1-1WT
  rect 2.54x1.651 smd: 1(-2.54,2.54) 2(-2.54,0) 3(-2.54,-2.54) 4(2.54,-2.54) 5(2.54,0) 6(2.54,2.54)
C0402_NO_SS
  rect 0.406x0.508 smd: 1(-0.508,0) 2(0.508,0)
CAP_A-CASE
  rect 1.524x1.27 smd: 1(-1.27,0) 2(1.27,0)
CON_RAPC722_JACK_THVT_3
  round 4.318 hole 3.556: 1(0,3.124)
  round 3.81 hole 3.048: 2(0,-3.124) 3(4.801,0.127)
CON_SMA-EDGE
  rect 3.556x0.635 smd: 1(0,0)
  rect 5.334x2.032 smd: 2(0.889,4.255) 3(0.889,-4.255) 4(0.889,-4.255) 5(0.889,4.255)
CON_SMRT_USBMNE20_F
  round 1.194 hole 1.168 unplated: (0.65,2.2) (0.65,-2.2)
  rect 2.311x0.508 smd: 1(3.45,1.6) 2(3.45,0.8) 3(3.45,0) 4(3.45,-0.8) 5(3.45,-1.6)
  rect 2.489x2.007 smd: 6(-2.15,-4.45) 7(3.35,-4.45) 8(3.35,4.45) 9(-2.15,4.45)
CON_SMVT_40X10_SEAM_MTG
  round 3.81 hole 2.692: (-31.496,-2.007) (31.496,-2.007)
  round 0.508 hole 1.27 unplated: (-27.191,-3.048) (27.191,0)
  round 0.635 smd: A1(24.765,5.715) A2(23.495,5.715) A3(22.225,5.715) A4(20.955,5.715) A5(19.685,5.715) A6(18.415,5.715) A7(17.145,5.715) A8(15.875,5.715) A9(14.605,5.715) A10(13.335,5.715) A11(12.065,5.715) A12(10.795,5.715) A13(9.525,5.715) A14(8.255,5.715) A15(6.985,5.715) A16(5.715,5.715) A17(4.445,5.715) A18(3.175,5.715) A19(1.905,5.715) A20(0.635,5.715) A21(-0.635,5.715) A22(-1.905,5.715) A23(-3.175,5.715) A24(-4.445,5.715) A25(-5.715,5.715) A26(-6.985,5.715) A27(-8.255,5.715) A28(-9.525,5.715) A29(-10.795,5.715) A30(-12.065,5.715) A31(-13.335,5.715) A32(-14.605,5.715) A33(-15.875,5.715) A34(-17.145,5.715) A35(-18.415,5.715) A36(-19.685,5.715) A37(-20.955,5.715) A38(-22.225,5.715) A39(-23.495,5.715) A40(-24.765,5.715) B1(24.765,4.445) B2(23.495,4.445) B3(22.225,4.445) B4(20.955,4.445) B5(19.685,4.445) B6(18.415,4.445) B7(17.145,4.445) B8(15.875,4.445) B9(14.605,4.445) B10(13.335,4.445) B11(12.065,4.445) B12(10.795,4.445) B13(9.525,4.445) B14(8.255,4.445) B15(6.985,4.445) B16(5.715,4.445) B17(4.445,4.445) B18(3.175,4.445) B19(1.905,4.445) B20(0.635,4.445) B21(-0.635,4.445) B22(-1.905,4.445) B23(-3.175,4.445) B24(-4.445,4.445) B25(-5.715,4.445) B26(-6.985,4.445) B27(-8.255,4.445) B28(-9.525,4.445) B29(-10.795,4.445) B30(-12.065,4.445) B31(-13.335,4.445) B32(-14.605,4.445) B33(-15.875,4.445) B34(-17.145,4.445) B35(-18.415,4.445) B36(-19.685,4.445) B37(-20.955,4.445) B38(-22.225,4.445) B39(-23.495,4.445) B40(-24.765,4.445) C1(24.765,3.175) C2(23.495,3.175) C3(22.225,3.175) C4(20.955,3.175) C5(19.685,3.175) C6(18.415,3.175) C7(17.145,3.175) C8(15.875,3.175) C9(14.605,3.175) C10(13.335,3.175) C11(12.065,3.175) C12(10.795,3.175) C13(9.525,3.175) C14(8.255,3.175) C15(6.985,3.175) C16(5.715,3.175) C17(4.445,3.175) C18(3.175,3.175) C19(1.905,3.175) C20(0.635,3.175) C21(-0.635,3.175) C22(-1.905,3.175) C23(-3.175,3.175) C24(-4.445,3.175) C25(-5.715,3.175) C26(-6.985,3.175) C27(-8.255,3.175) C28(-9.525,3.175) C29(-10.795,3.175) C30(-12.065,3.175) C31(-13.335,3.175) C32(-14.605,3.175) C33(-15.875,3.175) C34(-17.145,3.175) C35(-18.415,3.175) C36(-19.685,3.175) C37(-20.955,3.175) C38(-22.225,3.175) C39(-23.495,3.175) C40(-24.765,3.175) D1(24.765,1.905) D2(23.495,1.905) D3(22.225,1.905) D4(20.955,1.905) D5(19.685,1.905) D6(18.415,1.905) D7(17.145,1.905) D8(15.875,1.905) D9(14.605,1.905) D10(13.335,1.905) D11(12.065,1.905) D12(10.795,1.905) D13(9.525,1.905) D14(8.255,1.905) D15(6.985,1.905) D16(5.715,1.905) D17(4.445,1.905) D18(3.175,1.905) D19(1.905,1.905) D20(0.635,1.905) D21(-0.635,1.905) D22(-1.905,1.905) D23(-3.175,1.905) D24(-4.445,1.905) D25(-5.715,1.905) D26(-6.985,1.905) D27(-8.255,1.905) D28(-9.525,1.905) D29(-10.795,1.905) D30(-12.065,1.905) D31(-13.335,1.905) D32(-14.605,1.905) D33(-15.875,1.905) D34(-17.145,1.905) D35(-18.415,1.905) D36(-19.685,1.905) D37(-20.955,1.905) D38(-22.225,1.905) D39(-23.495,1.905) D40(-24.765,1.905) E1(24.765,0.635) E2(23.495,0.635) E3(22.225,0.635) E4(20.955,0.635) E5(19.685,0.635) E6(18.415,0.635) E7(17.145,0.635) E8(15.875,0.635) E9(14.605,0.635) E10(13.335,0.635) E11(12.065,0.635) E12(10.795,0.635) E13(9.525,0.635) E14(8.255,0.635) E15(6.985,0.635) E16(5.715,0.635) E17(4.445,0.635) E18(3.175,0.635) E19(1.905,0.635) E20(0.635,0.635) E21(-0.635,0.635) E22(-1.905,0.635) E23(-3.175,0.635) E24(-4.445,0.635) E25(-5.715,0.635) E26(-6.985,0.635) E27(-8.255,0.635) E28(-9.525,0.635) E29(-10.795,0.635) E30(-12.065,0.635) E31(-13.335,0.635) E32(-14.605,0.635) E33(-15.875,0.635) E34(-17.145,0.635) E35(-18.415,0.635) E36(-19.685,0.635) E37(-20.955,0.635) E38(-22.225,0.635) E39(-23.495,0.635) E40(-24.765,0.635) F1(24.765,-0.635) F2(23.495,-0.635) F3(22.225,-0.635) F4(20.955,-0.635) F5(19.685,-0.635) F6(18.415,-0.635) F7(17.145,-0.635) F8(15.875,-0.635) F9(14.605,-0.635) F10(13.335,-0.635) F11(12.065,-0.635) F12(10.795,-0.635) F13(9.525,-0.635) F14(8.255,-0.635) F15(6.985,-0.635) F16(5.715,-0.635) F17(4.445,-0.635) F18(3.175,-0.635) F19(1.905,-0.635) F20(0.635,-0.635) F21(-0.635,-0.635) F22(-1.905,-0.635) F23(-3.175,-0.635) F24(-4.445,-0.635) F25(-5.715,-0.635) F26(-6.985,-0.635) F27(-8.255,-0.635) F28(-9.525,-0.635) F29(-10.795,-0.635) F30(-12.065,-0.635) F31(-13.335,-0.635) F32(-14.605,-0.635) F33(-15.875,-0.635) F34(-17.145,-0.635) F35(-18.415,-0.635) F36(-19.685,-0.635) F37(-20.955,-0.635) F38(-22.225,-0.635) F39(-23.495,-0.635) F40(-24.765,-0.635) G1(24.765,-1.905) G2(23.495,-1.905) G3(22.225,-1.905) G4(20.955,-1.905) G5(19.685,-1.905) G6(18.415,-1.905) G7(17.145,-1.905) G8(15.875,-1.905) G9(14.605,-1.905) G10(13.335,-1.905) G11(12.065,-1.905) G12(10.795,-1.905) G13(9.525,-1.905) G14(8.255,-1.905) G15(6.985,-1.905) G16(5.715,-1.905) G17(4.445,-1.905) G18(3.175,-1.905) G19(1.905,-1.905) G20(0.635,-1.905) G21(-0.635,-1.905) G22(-1.905,-1.905) G23(-3.175,-1.905) G24(-4.445,-1.905) G25(-5.715,-1.905) G26(-6.985,-1.905) G27(-8.255,-1.905) G28(-9.525,-1.905) G29(-10.795,-1.905) G30(-12.065,-1.905) G31(-13.335,-1.905) G32(-14.605,-1.905) G33(-15.875,-1.905) G34(-17.145,-1.905) G35(-18.415,-1.905) G36(-19.685,-1.905) G37(-20.955,-1.905) G38(-22.225,-1.905) G39(-23.495,-1.905) G40(-24.765,-1.905) H1(24.765,-3.175) H2(23.495,-3.175) H3(22.225,-3.175) H4(20.955,-3.175) H5(19.685,-3.175) H6(18.415,-3.175) H7(17.145,-3.175) H8(15.875,-3.175) H9(14.605,-3.175) H10(13.335,-3.175) H11(12.065,-3.175) H12(10.795,-3.175) H13(9.525,-3.175) H14(8.255,-3.175) H15(6.985,-3.175) H16(5.715,-3.175) H17(4.445,-3.175) H18(3.175,-3.175) H19(1.905,-3.175) H20(0.635,-3.175) H21(-0.635,-3.175) H22(-1.905,-3.175) H23(-3.175,-3.175) H24(-4.445,-3.175) H25(-5.715,-3.175) H26(-6.985,-3.175) H27(-8.255,-3.175) H28(-9.525,-3.175) H29(-10.795,-3.175) H30(-12.065,-3.175) H31(-13.335,-3.175) H32(-14.605,-3.175) H33(-15.875,-3.175) H34(-17.145,-3.175) H35(-18.415,-3.175) H36(-19.685,-3.175) H37(-20.955,-3.175) H38(-22.225,-3.175) H39(-23.495,-3.175) H40(-24.765,-3.175) J1(24.765,-4.445) J2(23.495,-4.445) J3(22.225,-4.445) J4(20.955,-4.445) J5(19.685,-4.445) J6(18.415,-4.445) J7(17.145,-4.445) J8(15.875,-4.445) J9(14.605,-4.445) J10(13.335,-4.445) J11(12.065,-4.445) J12(10.795,-4.445) J13(9.525,-4.445) J14(8.255,-4.445) J15(6.985,-4.445) J16(5.715,-4.445) J17(4.445,-4.445) J18(3.175,-4.445) J19(1.905,-4.445) J20(0.635,-4.445) J21(-0.635,-4.445) J22(-1.905,-4.445) J23(-3.175,-4.445) J24(-4.445,-4.445) J25(-5.715,-4.445) J26(-6.985,-4.445) J27(-8.255,-4.445) J28(-9.525,-4.445) J29(-10.795,-4.445) J30(-12.065,-4.445) J31(-13.335,-4.445) J32(-14.605,-4.445) J33(-15.875,-4.445) J34(-17.145,-4.445) J35(-18.415,-4.445) J36(-19.685,-4.445) J37(-20.955,-4.445) J38(-22.225,-4.445) J39(-23.495,-4.445) J40(-24.765,-4.445) K1(24.765,-5.715) K2(23.495,-5.715) K3(22.225,-5.715) K4(20.955,-5.715) K5(19.685,-5.715) K6(18.415,-5.715) K7(17.145,-5.715) K8(15.875,-5.715) K9(14.605,-5.715) K10(13.335,-5.715) K11(12.065,-5.715) K12(10.795,-5.715) K13(9.525,-5.715) K14(8.255,-5.715) K15(6.985,-5.715) K16(5.715,-5.715) K17(4.445,-5.715) K18(3.175,-5.715) K19(1.905,-5.715) K20(0.635,-5.715) K21(-0.635,-5.715) K22(-1.905,-5.715) K23(-3.175,-5.715) K24(-4.445,-5.715) K25(-5.715,-5.715) K26(-6.985,-5.715) K27(-8.255,-5.715) K28(-9.525,-5.715) K29(-10.795,-5.715) K30(-12.065,-5.715) K31(-13.335,-5.715) K32(-14.605,-5.715) K33(-15.875,-5.715) K34(-17.145,-5.715) K35(-18.415,-5.715) K36(-19.685,-5.715) K37(-20.955,-5.715) K38(-22.225,-5.715) K39(-23.495,-5.715) K40(-24.765,-5.715)
CWX813
  rect 2x1.8 smd: 1(-2.095,2.54) 2(-2.095,-2.54) 3(2.095,-2.54) 4(2.095,2.54)
FT245RL
  oval 2.108x0.406 smd: 1(-3.45,4.225) 2(-3.45,3.575) 3(-3.45,2.925) 4(-3.45,2.275) 5(-3.45,1.625) 6(-3.45,0.975) 7(-3.45,0.325) 8(-3.45,-0.325) 9(-3.45,-0.975) 10(-3.45,-1.625) 11(-3.45,-2.275) 12(-3.45,-2.925) 13(-3.45,-3.575) 14(-3.45,-4.225) 15(3.45,-4.225) 16(3.45,-3.575) 17(3.45,-2.925) 18(3.45,-2.275) 19(3.45,-1.625) 20(3.45,-0.975) 21(3.45,-0.325) 22(3.45,0.325) 23(3.45,0.975) 24(3.45,1.625) 25(3.45,2.275) 26(3.45,2.925) 27(3.45,3.575) 28(3.45,4.225)
LED_0805
  rect 1.422x1.524 smd: 1(-1.143,0) 2(1.143,0)
MABA-007159-000000
  rect 0.762x1.397 smd: 1(-1.27,1.714) 2(0,1.714) 3(1.27,1.714) 4(1.27,-1.714) 5(0,-1.714) 6(-1.27,-1.714)
MFG125_PLATED
  round 3.556 hole 3.175: 1(0,0)
NFM41P
  rect 1.27x1.6 smd: 1(-2.413,0) 3(2.413,0)
  rect 1.778x2.54 smd: 2(0,0)
QFN_32_IRONWOOD_0P5MM
  round 2.286 hole 1.524: (-8,12)
  round 2 hole 2.438 unplated: (-8,8) (-8,-8) (8,8) (8,-8)
  round 2.52 hole 2.032: (8,-12)
  rect 0.85x0.28 smd: 1(-2.475,1.75) 2(-2.475,1.25) 3(-2.475,0.75) 4(-2.475,0.25) 5(-2.475,-0.25) 6(-2.475,-0.75) 7(-2.475,-1.25) 8(-2.475,-1.75) 17(2.475,-1.75) 18(2.475,-1.25) 19(2.475,-0.75) 20(2.475,-0.25) 21(2.475,0.25) 22(2.475,0.75) 23(2.475,1.25) 24(2.475,1.75)
  rect 0.28x0.85 smd: 9(-1.75,-2.475) 10(-1.25,-2.475) 11(-0.75,-2.475) 12(-0.25,-2.475) 13(0.25,-2.475) 14(0.75,-2.475) 15(1.25,-2.475) 16(1.75,-2.475) 25(1.75,2.475) 26(1.25,2.475) 27(0.75,2.475) 28(0.25,2.475) 29(-0.25,2.475) 30(-0.75,2.475) 31(-1.25,2.475) 32(-1.75,2.475)
  rect 3.45x3.45 smd: 33(0,0)
R0603
  rect 0.813x0.965 smd: 1(-0.711,0) 2(0.711,0)
SC-MKT-SDB06A_6LLP
  rect 0.61x0.254 smd: 1(-1.143,0.66) 2(-1.143,0) 3(-1.143,-0.66) 4(1.143,-0.66) 5(1.143,0) 6(1.143,0.66)
  rect 0.762x1.194 smd: 7(0,0)
SC-MKT-SDC08A_LLP
  rect 0.599x0.3 smd: 1(-1.9,1.199) 2(-1.9,0.399) 3(-1.9,-0.399) 4(-1.9,-1.199) 5(1.9,-1.199) 6(1.9,-0.399) 7(1.9,0.399) 8(1.9,1.199)
  rect 2.591x2.997 smd: DAP(0,0)
SMD_SIZE0402
  rect 0.635x0.508 smd: 1(-0.635,0) 2(0.635,0)
SMD_SIZE0603
  rect 0.762x0.965 smd: 1(-0.813,0) 2(0.813,0)
SMD_SIZE1206
  rect 1.27x1.778 smd: 1(-1.397,0) 2(1.397,0)
SMD_SIZE1812R
  rect 1.651x2.54 smd: 1(-2.223,0) 2(2.223,0)
SMD_SIZE3216
  rect 1.524x1.27 smd: 1(-1.27,0) 2(1.27,0)
SOIC6_100_WG272_L560
  rect 4.699x1.397 smd: 1(-3.454,2.54) 2(-3.454,0) 3(-3.454,-2.54) 4(3.454,-2.54) 5(3.454,0) 6(3.454,2.54)
SOT-723
  rect 0.4x0.46 smd: 1(-0.4,-0.575) 2(0.4,-0.575)
  rect 0.508x0.457 smd: 3(0,0.575)
SW_RESET_PTS635
  round 2.032 hole 1.397: 1(-3.251,0) 2(3.251,0)
TESTPOINT_62DIA
  round 2.337 hole 1.575: 1(0,0)
TP_THVT_100_RND
  round 2.54 hole 1.016: 1(0,0)
TP_THVT_100_RND_GND
  round 2.54 hole 1.016: 1(0,0)
TSSOP16_PW
  rect 1.45x0.25 smd: 1(-2.975,2.275) 2(-2.975,1.625) 3(-2.975,0.975) 4(-2.975,0.325) 5(-2.975,-0.325) 6(-2.975,-0.975) 7(-2.975,-1.625) 8(-2.975,-2.275) 9(2.975,-2.275) 10(2.975,-1.625) 11(2.975,-0.975) 12(2.975,-0.325) 13(2.975,0.325) 14(2.975,0.975) 15(2.975,1.625) 16(2.975,2.275)
unnamed#2
  round 1.016 smd: (0,0)
WQFN_64_360X360_0P5MM_PWRPAD
  rect 0.6x0.25 smd: 1(-4.395,3.753) 2(-4.395,3.252) 3(-4.395,2.752) 4(-4.395,2.252) 5(-4.395,1.751) 6(-4.395,1.251) 7(-4.395,0.751) 8(-4.395,0.25) 9(-4.395,-0.25) 10(-4.395,-0.751) 11(-4.395,-1.251) 12(-4.395,-1.751) 13(-4.395,-2.252) 14(-4.395,-2.752) 15(-4.395,-3.252) 16(-4.395,-3.753) 33(4.395,-3.753) 34(4.395,-3.252) 35(4.395,-2.752) 36(4.395,-2.252) 37(4.395,-1.751) 38(4.395,-1.251) 39(4.395,-0.751) 40(4.395,-0.25) 41(4.395,0.25) 42(4.395,0.751) 43(4.395,1.251) 44(4.395,1.751) 45(4.395,2.252) 46(4.395,2.752) 47(4.395,3.252) 48(4.395,3.753)
  rect 0.25x0.6 smd: 17(-3.753,-4.395) 18(-3.252,-4.395) 19(-2.752,-4.395) 20(-2.252,-4.395) 21(-1.751,-4.395) 22(-1.251,-4.395) 23(-0.751,-4.395) 24(-0.25,-4.395) 25(0.25,-4.395) 26(0.751,-4.395) 27(1.251,-4.395) 28(1.751,-4.395) 29(2.252,-4.395) 30(2.752,-4.395) 31(3.252,-4.395) 32(3.753,-4.395) 49(3.753,4.395) 50(3.252,4.395) 51(2.752,4.395) 52(2.252,4.395) 53(1.751,4.395) 54(1.251,4.395) 55(0.751,4.395) 56(0.25,4.395) 57(-0.25,4.395) 58(-0.751,4.395) 59(-1.251,4.395) 60(-1.751,4.395) 61(-2.252,4.395) 62(-2.752,4.395) 63(-3.252,4.395) 64(-3.753,4.395)
  rect 7.188x7.188 smd: 65(0,0)
ZENER_DO_214AC
  rect 1.321x1.676 smd: 1(1.854,0) 2(-1.854,0)

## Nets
+5V: C103.1 C105.1 C114.1 C116.1 C125.1 C127.1 C137.1 C139.1 J1.1 R81.1 R96.1 TP21.1(TP) U8.4(IN) U9.4(IN) U10.4(IN) U11.4(IN)
GND: C1.2 C2.2 C3.1 C4.1 C5.1 C7.2 C8.2 C9.2 C10.2 C11.2 C12.2 C13.2 C14.2 C15.2 C16.2 C17.2 C18.2 C22.2 C23.2 C24.2 C25.2 C26.2 C27.2 C29.1 C31.2 C32.2 C34.2 C35.2 C43.2 C44.2 C45.2 C47.2 C48.2 C55.1 C56.2 C57.2 C58.2 C59.2 C60.2 C61.2 C63.2 C64.2 C65.2 C66.1 C82.1 C83.1 C87.1 C92.2 C93.2 C99.2 C103.2 C104.2 C105.2 C106.1 C108.2 C109.2 C110.1 C111.2 C112.2 C113.2 C114.2 C115.2 C116.2 C117.1 C118.2 C119.1 C121.2 C122.2 C123.2 C125.2 C126.2 C127.2 C128.2 C131.2 C132.2 C133.2 C134.2 C136.2 C137.2 C139.2 C140.2 C141.2 C144.2 C145.2 C146.2 C152.2 C160.2 C164.2 C179.2 C195.1 C197.1 C199.2 C200.2 C201.2 C202.2 C203.2 C204.2 C205.2 C206.2 J1.2 J1.3 J2.2(SHIELD2) J2.3(SHIELD3) J2.4(SHIELD4) J2.5(SHIELD5) J3.2(SHIELD2) J3.3(SHIELD3) J3.4(SHIELD4) J3.5(SHIELD5) J4.2(SHIELD2) J4.3(SHIELD3) J4.4(SHIELD4) J4.5(SHIELD5) J5.2(SHIELD2) J5.3(SHIELD3) J5.4(SHIELD4) J5.5(SHIELD5) J6.2(SHIELD2) J6.3(SHIELD3) J6.4(SHIELD4) J6.5(SHIELD5) J7.2(SHIELD2) J7.3(SHIELD3) J7.4(SHIELD4) J7.5(SHIELD5) J8.A1 J8.A4 J8.A5 J8.A8 J8.A9 J8.A12 J8.A13 J8.A16 J8.A17 J8.A20 J8.A21 J8.A24 J8.A25 J8.A28 J8.A29 J8.A32 J8.A33 J8.A36 J8.A37 J8.A40 J8.B2 J8.B3 J8.B6 J8.B7 J8.B10 J8.B11 J8.B15 J8.B18 J8.B19 J8.B22 J8.B23 J8.B26 J8.B27 J8.B30 J8.B31 J8.B34 J8.B35 J8.B38 J8.B39 J8.C1 J8.C4 J8.C5 J8.C8 J8.C9 J8.C12 J8.C13 J8.C16 J8.C17 J8.C20 J8.C21 J8.C24 J8.C25 J8.C28 J8.C29 J8.C32 J8.C33 J8.C36 J8.C38 J8.C40 J8.D2 J8.D3 J8.D6 J8.D7 J8.D10 J8.D13 J8.D16 J8.D19 J8.D22 J8.D25 J8.D28 J8.D37 J8.D39 J8.E1 J8.E4 J8.E5 J8.E8 J8.E11 J8.E14 J8.E17 J8.E20 J8.E23 J8.E26 J8.E29 J8.E32 J8.E35 J8.E38 J8.E40 J8.F2 J8.F3 J8.F6 J8.F9 J8.F12 J8.F15 J8.F18 J8.F21 J8.F24 J8.F27 J8.F30 J8.F33 J8.F36 J8.F39 J8.G1 J8.G4 J8.G5 J8.G8 J8.G11 J8.G14 J8.G17 J8.G20 J8.G23 J8.G26 J8.G29 J8.G32 J8.G35 J8.G38 J8.G40 J8.H2 J8.H3 J8.H6 J8.H9 J8.H12 J8.H15 J8.H18 J8.H21 J8.H24 J8.H27 J8.H30 J8.H33 J8.H36 J8.H39 J8.J1 J8.J4 J8.J5 J8.J8 J8.J11 J8.J14 J8.J17 J8.J20 J8.J23 J8.J26 J8.J29 J8.J32 J8.J35 J8.J38 J8.J40 J8.K2 J8.K3 J8.K6 J8.K9 J8.K12 J8.K15 J8.K18 J8.K21 J8.K24 J8.K27 J8.K30 J8.K33 J8.K36 J8.K39 LF1_C1.2 LF1_R2.2 LF2_C1.2 LF2_R2.2 Q1.2(S) R1.2 R2.2 R4.1 R14.2 R19.2 R20.2 R22.2 R23.2 R27.1 R32.1 R35.1 R36.1 R39.1 R46.1 R47.1 R48.1 R49.1 R52.2 R53.2 R54.1 R55.1 R63.2 R66.2 R69.2 R79.2 R82.2 R87.1 R89.1 R90.1 R97.2 R102.1 R110.2 R111.2 R120.2 R155.2 T5.2 T5.3 T5.5 TP1.1(TP) TP9.1(TP) TP10.1(TP) TP11.1(TP) TP12.1(TP) TP22.1(TP) U1.2(AGND_2) U1.5(AGND_5) U1.8(AGND_8) U1.11(AGND_11) U1.18(AGND_18) U1.21(AGND_21) U1.27(AGND_27) U1.30(AGND_30) U1.31(AGND_31) U1.33(DAP) U5.1(DIR1) U5.2(DIR2) U5.8(DIR4) U5.10(GND) U5.14(B1) U8.3(GND) U8.DAP U9.3(GND) U9.DAP U10.3(GND) U10.DAP U11.3(GND) U11.DAP U13.65(DAP) Y1.3(GND) Y2.2(GND) Y3.3(GND) Z2.2 Z2.3 Z4.2 Z5.2 Z6.2 Z7.2 Z8.2 Z9.2 Z10.2
GND2: C84.2 C86.2 C95.2 C96.2 C102.2 C158.2 C161.2 C162.2 J9.5(GND) J9.6(GND1) J9.7(GND2) J9.8(GND3) J9.9(GND4) TP13.1(TP) U6.7(GND_7) U6.18(GND_18) U6.21(GND_21) U6.25(AGND) U6.26(TEST) U7.3(GND) U7.7(DAP) Z1.2 Z2.1 Z3.2
VIN+: R24.2 U1.3(VIN+)
VIN-: R25.2 U1.4(VIN-)
VINN: R4.2 R15.2 T1.4
VINN+: C17.1 C19.1 R3.2 R7.1 R13.2 R24.1
VINN-: C19.2 C23.1 R6.2 R9.1 R10.2 R25.1
VINP: R11.2 R14.1 T1.6
ADC_CSB: R77.2 R83.1 R85.1 R95.2 U1.23(CSB)
ADC_SCLK: R70.2 R92.2 U1.24(SCLK)
ADC_SDI: R73.2 R93.1 U1.25(SDI)
ADC_SDO: R72.2 R94.1 U1.26(SDO)
BP2P5: C43.1 C44.1 C45.1 TP14.1(TP) U1.22(BP2.5)
CLKIN+: R18.2 R40.2 R43.2 U1.9(CLKIN+)
CLKIN-: R18.1 R41.2 R50.2 U1.10(CLKIN-)
CLKOUT2+: C71.1 R49.2 U13.15(DCLKOUT2)
CLKOUT2-: C70.1 R48.2 U13.16(DCLKOUT2*)
CLKOUT3+: C69.1 R47.2 U13.13(SDCLKOUT3)
CLKOUT3-: C68.1 R46.2 U13.14(SDCLKOUT3*)
CLKOUT4+: C81.1 R55.2 U13.24(DCLKOUT4)
CLKOUT4-: C80.1 R54.2 U13.25(DCLKOUT4*)
CLKOUT8+: R165.1 U13.51(DCLKOUT8)
CLKOUT8-: R164.1 U13.52(DCLKOUT8*)
CLKOUT10+: R163.1 U13.54(DCLKOUT10)
CLKOUT10-: R162.1 U13.55(DCLKOUT10*)
CLKOUT11+: R161.1 U13.56(SDCLKOUT11)
CLKOUT11-: R160.1 U13.57(SDCLKOUT11*)
CSB_LMK_3P3: R57.2 U13.18(CS*)
EXT_CLK+: R40.1 T3.4
EXT_CLK-: R41.1 T3.6
EXT_REF: J7.1(CENTER) R34.1 R35.2
EXT_SYSREF+: R44.1 T4.4
EXT_SYSREF-: R45.1 T4.6
EXTREF: R17.2 R20.1 R227.2
EXTREF_XO: C159.1 R33.1 R34.2 R36.2 R227.1
EXTXO: R33.2 Y1.4(RF) Y2.3(OUT)
FMC_FPGA_DEVCLKA+: J8.D4 R165.2
FMC_FPGA_DEVCLKA-: J8.D5 R164.2
FMC_FPGA_DEVCLKB+: J8.G6 R163.2
FMC_FPGA_DEVCLKB-: J8.G7 R162.2
FMC_FPGA_SYSREF+: J8.G9 R161.2
FMC_FPGA_SYSREF-: J8.G10 R160.2
LMK_ADC_DEVCLK+: C70.2 R43.1
LMK_ADC_DEVCLK-: C71.2 R50.1
LMK_ADC_SYSREF+: C68.2 R51.1
LMK_ADC_SYSREF-: C69.2 R61.1
LMK_CSB: R75.2 R84.1 U5.13(B2)
LMK_DIR: R27.2 R74.2 U5.7(DIR3)
LMK_RESET: C110.2 R110.1 R112.2 R113.2 U13.5(RESET)
LMK_RESET_FMC: J8.G24 R113.1
LMK_SCLK: R71.2 U5.11(B4)
LMK_SDIO: R76.2 U5.12(B3)
LMK_SYNC: C117.2 R111.1 R114.2 R115.2 U13.6(SYNC)
LMK_SYNC_FMC: J8.G25 R114.1
LMK_VCC1/5/6: C61.1 C118.1 C160.1 C199.1 L3.1 U13.10(VCC1_VCO) U13.33(VCC5_DIG) U13.36(VCC6_PLL1)
LMK_VCC2: C152.1 L4.2 U13.17(VCC2_CG1)
LMK_VCC3: C200.1 L9.2 U13.21(VCC3_SYSREF)
LMK_VCC4: C201.1 L10.2 U13.26(VCC4_CG2)
LMK_VCC7: C206.1 L13.2 U13.39(VCC7_OSCOUT)
LMK_VCC8/10: C141.1 C164.1 C204.1 L5.1 L13.1 L14.1 U13.42(VCC8_OSCIN) U13.47(VCC10_PLL2)
LMK_VCC9: C205.1 L14.2 U13.45(VCC9_CP2)
LMK_VCC11: C202.1 L11.2 U13.53(VCC11_CG3)
LMK_VCC12: C203.1 L12.2 U13.64(VCC12_CG0)
PG_C2M: J8.D1 R155.1
PG_M2C: J8.F1 R156.2
REFCLK: J6.1(CENTER) T5.1
REFCLK+: C81.2 T5.6
REFCLK-: C80.2 T5.4
SCLK_LMK_3P3: R58.2 U13.19(SCK)
SDIO_LMK_3P3: R59.2 U13.20(SDIO)
SO+: C37.2 J8.C6
SO-: C36.2 J8.C7
SSYSREF+: C186.2 R29.2 R44.2 R51.2
SSYSREF-: C187.2 R29.1 R45.2 R61.2
STATUS_LD1: TP19.1(TP) U13.31(STATUS_LD1)
STATUS_LD2: TP18.1(TP) U13.48(STATUS_LD2)
SYNCB+: J8.G12 U1.15(SYNCB+)
SYNCB-: J8.G13 U1.16(SYNCB-)
SYSREF+: C186.1 R119.1 U1.13(SYSREF+)
SYSREF-: C179.1 C187.1 U1.14(SYSREF-)
T1+: C20.1 T1.1
T1-: C21.1 T1.3
V_VCXO3.3: C59.1 C60.1 C140.1 C146.1 L8.1 TP8.1(TP) Z10.3
V_XO3.3: C58.1 C134.1 C136.1 R31.2 TP7.1(TP) Y1.6(VS) Y2.4(VCC) Z9.3
VA1.2: C3.2 C5.2 C9.1 C10.1 C11.1 C12.1 C99.1 C104.1 SW3.1 TP2.1(TP) U1.7(VA1.2_7) U1.28(VA1.2_28) Z4.3
VA1.2_AUX: C4.2 C34.1 C35.1 C111.1 C112.1 TP3.1(TP) U1.17(VA1.2_17) Z5.3
VA1.8: C7.1 C8.1 C13.1 C15.1 C18.1 C24.1 C113.1 C115.1 R83.2 R84.2 TP4.1(TP) U1.12(VA1.8_12) U1.29(VA1.8_29) U1.32(VA1.8_32) Z6.3
VA3.0: C1.1 C2.1 C123.1 C126.1 R28.1 R65.2 R68.1 TP5.1(TP) U1.1(VA3.0) Z7.3
VADJ: J8.E39 J8.F40 J8.G39 J8.H40 R42.1 R156.1
VCM: C22.1 C32.1 R7.2 R8.2 R9.2 R16.1 TP15.1(TP)
VCMODE: C25.1 C26.1 C27.1 R16.2 U1.6(VCM)
VIO_B_M2C: J8.J39 J8.K40 R42.2
VLMK3.3: C82.2 C92.1 C93.1 C128.1 C133.1 L3.2 L4.1 L5.2 L9.1 L10.1 L11.1 L12.1 R86.1 SW1.1 SW2.1 TP6.1(TP) U5.16(VCCA) Z8.3
VN: J3.1(CENTER) R5.1 R15.1
VP: J2.1(CENTER) R11.1 R12.1
VSPI1.8: C83.2 C95.1 C162.1 R60.2 R85.2 TP20.1(TP) U5.15(VCCB) U6.4(VCCIO) Z3.3
N17161280: C129.1 C132.1 R56.2 R78.2 U10.5(OUT) Z7.1
N17161284: R96.2 R97.1 U10.8(S\D\)
N17161345: C129.2 R69.1 R78.1 U10.6(ADJ)
N17161357: C131.1 U10.1(BYPASS)
N17161499: C142.1 C145.1 R80.2 U11.5(OUT) Z8.1 Z9.1 Z10.1
N17161629: R81.2 R82.1 U11.8(S\D\)
N17161669: C142.2 R79.1 R80.1 U11.6(ADJ)
N17161679: C144.1 U11.1(BYPASS)
N17161879: C107.1 C109.1 D2.1(ANODE) R64.2 U8.5(OUT) Z4.1 Z5.1
N17161936: C106.2 R65.1 R89.2 U8.8(S\D\)
N17162041: C120.1 C122.1 D1.1(ANODE) R62.2 R67.2 U9.5(OUT) Z6.1
N17162051: C119.2 R68.2 R90.2 U9.8(S\D\)
N17162120: C120.2 R66.1 R67.1 U9.6(ADJ)
N17162132: C121.1 U9.1(BYPASS)
N17162350: C107.2 R63.1 R64.1 U8.6(ADJ)
N17162360: C108.1 U8.1(BYPASS)
N17167241: C158.1 J9.2(D-) U6.16(USBDM)
N17167387: C102.1 U7.1(VOUT) Z3.1
N17167421: C96.1 R157.2 U7.4(EN) U7.6(VIN)
N17167654: R70.1 U6.1(D0)
N17167656: R73.1 U6.5(D1)
N17167658: R72.1 U6.3(D2)
N17167660: R77.1 U6.11(D3)
N17167662: R71.1 U6.2(D4)
N17167664: R75.1 U6.9(D5)
N17167666: R76.1 U6.10(D6)
N17167668: R74.1 U6.6(D7)
N17167775: R58.1 U5.6(A4)
N17167777: R59.1 U5.5(A3)
N17167779: R57.1 U5.4(A2)
N17167819: C86.1 J9.3(D+) U6.15(USBDP)
N17168074: C84.1 U6.17(3V3OUT)
N17168078: R60.1 U6.12(P\W\R\E\N\)
N17168092: J9.1(VBUS) Z1.1
N17168106: C161.1 R158.2 U6.20(VCC)
N17215258: C16.1 T1.2 T1.5
N17215302: C20.2 T2.6
N17215394: C14.1 R8.1 T2.2 T2.5
N17215600: R3.1 T2.1
N17215624: C21.2 T2.4
N17215642: R10.1 T2.3
N17220421: C31.1 T3.2 T3.5
N17225099: C56.1 T4.2 T4.5
N17242573: C36.1 U1.20(SO-)
N17242594: C37.1 U1.19(SO+)
N17273940: R157.1 R158.1 Z1.3
N17303725: LF2_C1.1 LF2_C2.1 U13.46(CPOUT2)
N17303875: C63.1 R37.2 Y3.1(VTUNE)
N17303984: C64.1 C65.1 L8.2 Y3.6(VS)
N17304319: LF2_C2.2 LF2_R2.1
N17304368: R38.2 Y3.4(RF)
N17304374: C51.2 R38.1 R39.2
N17304410: C57.1 R31.1 R32.2 Y1.1(VTUNE) Y2.1(EN)
N17304458: C66.2 U13.44(OSCIN*)
N17304625: LF1_C1.1 LF1_C2.1 R37.1 U13.32(CPOUT1)
N17305040: C51.1 C67.1 R30.1
N17305042: C67.2 U13.43(OSCIN)
N17305088: C195.2 U13.35(CLKIN1*/FIN*/FBCLKIN*)
N17305090: C159.2 C196.1 C198.1 R30.2
N17305092: C196.2 U13.34(CLKIN1/FIN/FBCLKIN)
N17305106: C197.2 U13.38(CLKIN0*)
N17305110: C198.2 U13.37(CLKIN0)
N17305389: R112.1 SW2.2
N17305438: R115.1 SW1.2
N17320541: TP16.1(TP) U13.59(CLKIN_SEL1)
N17320545: TP17.1(TP) U13.58(CLKIN_SEL0)
N17320732: C47.1 U13.12(LDOBYP2)
N17320734: C48.1 U13.11(LDOBYP1)
N17329800: C87.2 R119.2 R120.1 SW3.2
N17424784: J8.D31 R116.2
N17424792: J8.D30 R116.1
N17424855: J8.H31 Q1.1(G) R102.2
N17425083: J8.H37 R92.1
N17425085: J8.H38 R95.1
N17425095: Q1.3(D) SYNC.2(CATHODE)
N17425908: J8.G36 R93.2
N17425910: J8.G37 R94.2
N17439983: LF1_C2.2 LF1_R2.1
N17456786: C28.1 J4.1(CENTER) R21.2 R22.1
N17456846: C53.1 J5.1(CENTER) R23.1
N17469287: R1.1 R12.2 R13.1 R52.1
N17469485: R2.1 R5.2 R6.1 R53.1
N17474156: C53.2 T4.3
N17474169: C55.2 T4.1
N17474172: C29.2 T3.1
N17474175: C28.2 T3.3
N17476146: R17.1 R19.1 R21.1
N17481569: R86.2 R87.2 U5.9(OEB)
N17576943: D2.2(CATHODE) R62.1
N17577005: D1.2(CATHODE) R56.1
N174249330: R28.2 SYNC.1(ANODE)

Pads without a net: J8 A2 A3 A6 A7 A10 A11 A14 A15 A18 A19 A22 A23 A26 A27 A30 A31 A34 A35 A38 A39 B1 B4 B5 B8 B9 B12 B13 B14 B16 B17 B20 B21 B24 B25 B28 B29 B32 B33 B36 B37 B40 C2 C3 C10 C11 C14 C15 C18 C19 C22 C23 C26 C27 C30 C31 C34 C35 C37 C39 D8 D9 D11 D12 D14 D15 D17 D18 D20 D21 D23 D24 D26 D27 D29 D32 D33 D34 D35 D36 D38 D40 E2 E3 E6 E7 E9 E10 E12 E13 E15 E16 E18 E19 E21 E22 E24 E25 E27 E28 E30 E31 E33 E34 E36 E37 F4 F5 F7 F8 F10 F11 F13 F14 F16 F17 F19 F20 F22 F23 F25 F26 F28 F29 F31 F32 F34 F35 F37 F38 G2 G3 G15 G16 G18 G19 G21 G22 G27 G28 G30 G31 G33 G34 H1 H4 H5 H7 H8 H10 H11 H13 H14 H16 H17 H19 H20 H22 H23 H25 H26 H28 H29 H32 H34 H35 J2 J3 J6 J7 J9 J10 J12 J13 J15 J16 J18 J19 J21 J22 J24 J25 J27 J28 J30 J31 J33 J34 J36 J37 K1 K4 K5 K7 K8 K10 K11 K13 K14 K16 K17 K19 K20 K22 K23 K25 K26 K28 K29 K31 K32 K34 K35 K37 K38; J9 4; MT1 1; MT2 1; MT3 1; MT4 1; U5 3; U6 8 13 14 19 22 23 24 27 28; U7 2 5; U8 2 7; U9 2 7; U10 2 7; U11 2 7; U13 1 2 3 4 7 8 9 22 23 27 28 29 30 40 41 49 50 60 61 62 63; Y1 2 5; Y3 2 5

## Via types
v1: diameter 0.406, hole 0.305, TOP to BOTTOM, 903 vias
v2: diameter 0.559, hole 0.305, TOP to BOTTOM, 1368 vias
v3: diameter 1.524, hole 0.914, TOP to BOTTOM, 4 vias
v4: diameter 0.508, hole 0.254, TOP to BOTTOM, 16 vias
v5: diameter 0.4, hole 0.203, TOP to BOTTOM, 30 vias

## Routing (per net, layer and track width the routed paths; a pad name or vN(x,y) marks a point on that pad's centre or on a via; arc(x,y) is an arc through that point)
+5V: length 21.7
  TOP w0.305: C116.1 v2(10.52,42.99) U9.4 ; C105.1 U8.4 ; U10.4 v2(10.52,55.69) C127.1 ; U11.4 v2(90.92,17.4) C139.1
  TOP w1.27: C114.1 C116.1 ; C137.1 C139.1 ; C125.1 C127.1
  L3_POWER w0.508: 82.75,14.15 82.78,14.12 ; 83.06,13.34 83.13,13.41
  BOTTOM w0.508: v2(94.95,14.29) 94.95,16.5 94.52,16.93 91.39,16.93 v2(90.92,17.4)
  vias: v2(7.41,51.66) v2(11.15,56.05) v2(11.15,55.34) v2(11.15,43.35) v2(11.15,42.64) v2(12.37,56.05) v2(12.37,55.34) v2(12.37,43.35) v2(12.37,42.64) v2(13.95,56.18) v2(13.95,55.21) v2(13.95,43.48) v2(13.95,42.51) v2(14.66,56.18) v2(14.66,55.21) v2(14.66,43.48) v2(14.66,42.51) v2(68.03,106.38) v2(68.03,105.16) v2(68.73,106.38) v2(68.73,105.16) v2(90.44,21.54) v2(90.44,20.83) v2(90.57,19.26) v2(90.57,18.04) v2(91.27,19.26) v2(91.27,18.04) v2(91.4,21.54) v2(91.4,20.83)
GND: length 253.4
  TOP w0.203: 50.55,81.87 50.24,81.57 50.06,81.57 49.49,81 U1.27 ; 52.04,76.85 52.04,76.86 ; 45.52,79.35 45.52,79.36 ; v1(47.98,75.01) 47.98,74.63 ; C24.2 47.5,74.14 C18.2
  TOP w0.254: C24.2 v1(47.87,74.52) 47.99,74.64 U1.11 ; C25.2 44.58,77.68 C11.2 ; C8.2 47.57,81.55 47.49,81.47 U1.31 ; v1(44.81,79.4) 44.68,79.53 C1.2 ; v1(51.95,78.35) 51.95,78.36 U1.21 ; U1.5 45.5,77.85 v1(45.5,77.86) ; v1(45.51,79.37) 45.52,79.36 U1.2 ; v2(60.58,13.21) 60.65,13.14 U5.10 ; 47.99,81.45 U1.30 ; v1(46,76.35) U1.8 ; U1.18 52.04,76.85
  TOP w0.33: v2(2.73,79.85) J2.3 v2(2.73,81.29) ; v1(45.5,77.86) v1(44.83,77.86) C25.2 ; v2(72.26,2.73) J6.3 v2(73.7,2.73) ; C83.1 v1(63.96,8.23) ; v1(39.31,79.01) 39.31,78.66 ; 39.31,78.66 39.36,78.61 v1(40.09,78.61) ; 39.31,78.66 v1(39.31,78.61) C23.2 ; v2(65.19,2.73) J6.2 v2(63.75,2.73) ; C2.2 v1(44.81,79.4) 45.48,79.4 v1(45.51,79.37) ; v2(2.73,88.36) J2.2 v2(2.73,89.8) ; v1(48.16,82.98) C15.2 48.16,82.47 48.34,82.3 C13.2 48.3,81.96 48.3,81.75 47.99,81.45 ; U10.3 8.04,54.89 v2(8.04,54.5) ; 80.09,44 v2(80.75,44) ; v1(53.47,76.83) 53.42,76.89 v1(52.7,76.89) v1(52.07,76.89) 52.04,76.86 ; v1(45.44,75.91) 45.89,76.35 v1(46,76.35) ; v2(77.89,2.73) J7.2 v2(76.45,2.73) ; v2(2.73,75.92) J3.2 v2(2.73,77.36) ; v1(47.5,82.96) C7.2 47.5,82.07 C8.2 47.49,81.91 ; v2(2.73,68.85) J3.3 v2(2.73,67.41) ; v2(56.66,2.73) J5.3 v2(58.1,2.73) ; v2(45.4,2.73) J4.3 v2(43.96,2.73) ; v1(50.88,83.67) C9.2 50.88,82.32 C10.2 50.55,81.87 ; v2(36.89,2.73) J4.2 v2(35.45,2.73) ; v2(63.9,16.82) U5.2 ; v1(63.07,10.39) 63.25,10.57 U5.14 ; U8.3 69.18,102.04 v2(69.58,102.04) ; v2(64.7,44.35) R47.1 R46.1 v2(64.7,42.11) R49.1 R48.1 v2(64.7,39.88) ; 80.09,42.5 v2(80.75,42.5) ; v2(86.4,2.73) J7.3 v2(84.96,2.73) ; 95.81,101.09 v2(94.74,101.09) ; U9.3 8.04,42.19 v2(8.04,41.8) ; LF2_C1.2 v2(81.71,48.53) v2(81.71,49.44) ; v2(49.59,2.73) J5.2 v2(48.15,2.73) ; v2(92.12,14.92) 91.72,14.92 U11.3 ; C60.2 v2(85.37,57.62) ; v1(53.89,78.49) v1(53.21,78.49) 53.19,78.51 v1(52.45,78.51) 52.1,78.51 v1(51.95,78.35) ; v2(60,16.82) U5.8 ; v2(64.55,16.82) U5.1
  TOP w0.508: v2(43.33,34.9) 43.14,34.71 R19.2 42.25,34.71 v2(42.04,34.92) ; v2(45.64,34.9) 45.83,34.71 R20.2
  BOTTOM w0.203: 113.67,73.91 J8.A20
  BOTTOM w0.33: v2(42.72,74.96) 42.72,75.16 42.42,75.46 C3.1
  BOTTOM w0.381: v1(40.59,79.02) 40.08,79.53 39.62,79.53 39.21,79.13 ; 39.31,78.67 39.21,78.77 39.21,79.13 ; 39.21,79.13 C32.2 ; v1(53.47,76.83) 53.72,77.09 C4.1
  BOTTOM w0.406: v2(71.84,38.04) R55.1 R54.1 v2(74.12,38.04)
  BOTTOM w0.508: v5(76.39,47.17) 76.57,47.35 C205.2 ; J8.B6 v1(113.02,91.06) ; J8.A25 v1(113.02,66.93) ; J8.K9 v1(101.59,88.52) ; J8.J1 v1(102.86,98.68) ; J8.C21 v1(110.48,72.01) ; J8.H15 v1(104.13,80.9) ; J8.G1 v1(105.4,98.68) ; J8.A8 v1(113.02,89.79) ; J8.B7 v1(111.75,89.79) ; v5(76.39,45.8) 76.42,45.8 C204.2 ; J8.D37 v1(110.48,52.96) ; J8.H12 v1(104.13,84.71) ; J8.F9 v1(106.67,88.52) ; v5(70.95,41.74) 71.36,41.33 C200.2 ; J8.F39 v1(107.94,50.42) ; J8.B38 v1(111.75,50.42) ; J8.E1 v1(107.94,98.68) ; J8.E20 v1(107.94,73.28) ; J8.K36 v1(101.59,54.23) ; 69.25,48.9 69.27,48.9 v1(69.67,48.49) ; J8.G40 v1(105.4,47.88) ; J8.J26 v1(102.86,65.66) ; J8.D39 v1(110.48,50.42) ; J8.H18 v1(104.13,75.82) ; J8.B27 v1(111.75,64.39) ; J8.H36 v1(104.13,54.23) ; J8.J23 v1(102.86,69.47) ; J8.C32 v1(110.48,58.04) ; J8.A13 v1(113.02,83.44) ; C141.2 v1(76.07,45.12) ; J8.J20 v1(102.86,73.28) ; J8.K30 v1(101.59,60.58) ; J8.A32 v1(113.02,58.04) ; J8.C20 v1(110.48,73.28) ; J8.F27 v1(106.67,64.39) ; J8.F30 v1(106.67,60.58) ; J8.A37 v1(113.02,51.69) ; C118.2 v1(69.9,45.24) ; J8.B31 v1(111.75,59.31) ; J8.C13 v1(110.48,83.44) ; J8.C5 v1(111.75,92.33) ; v1(110.48,98.68) J8.C1 v1(111.75,97.41) J8.B2 ; J8.D6 v1(109.21,91.06) J8.D7 ; J8.J35 v1(102.86,54.23) ; J8.A1 v1(113.02,98.68) ; J8.A5 v1(113.02,92.33) ; J8.F24 v1(106.67,68.2) ; v5(76.39,44.43) 76.47,44.36 C206.2 ; C199.2 76.49,42.96 v5(76.39,43.06) ; J8.K2 v1(101.59,97.41) ; v5(75.07,48.5) 74.76,48.8 74.76,48.9 ; J8.C9 v1(110.48,88.52) ; J8.H2 v1(104.13,97.41) ; J8.G23 v1(105.4,69.47) ; J8.A40 v1(113.02,47.88) ; J8.G32 v1(105.4,58.04) ; J8.D3 v1(109.21,96.14) ; J8.H3 v1(104.13,96.14) ; J8.G35 v1(105.4,54.23) ; J8.G29 v1(105.4,61.85) ; J8.G8 v1(105.4,88.52) ; J8.J38 v1(102.86,50.42) ; J8.A24 v1(113.02,68.2) ; J8.J11 v1(102.86,84.71) ; J8.J14 v1(102.86,82.17) ; J8.C4 v1(111.75,93.6) ; J8.C28 v1(110.48,63.12) ; C201.2 73.8,41.64 v5(73.7,41.74) ; J8.A16 v1(114.29,78.36) ; J8.K21 v1(101.59,72.01) ; v1(76.3,41.78) 76.49,41.58 C160.2 ; J8.A12 v1(113.02,84.71) ; J8.B15 v1(111.75,80.9) ; C164.2 v1(76.42,48.37) ; J8.A9 v1(113.02,88.52) ; J8.K12 v1(101.59,84.71) ; J8.E11 v1(107.94,84.71) ; J8.H39 v1(104.13,49.15) ; J8.F2 v1(106.67,97.41) ; J8.H6 v1(104.13,92.33) ; J8.F15 v1(106.67,80.9) ; v1(69.59,41.78) 69.15,41.34 C152.2 ; J8.E26 v1(107.94,65.66) ; J8.E14 v1(107.94,82.17) ; J8.E4 v1(107.94,94.87) ; J8.J40 v1(102.86,47.88) ; J8.B19 v1(113.02,75.82) ; J8.E8 v1(107.94,88.52) ; J8.B10 v1(113.02,85.98) ; J8.H30 v1(104.13,60.58) ; J8.C25 v1(110.48,66.93) ; J8.G17 v1(105.4,78.36) ; J8.F3 v1(106.67,96.14) ; J8.F6 v1(106.67,91.06) ; J8.B11 v1(111.75,85.98) ; J8.E23 v1(107.94,69.47) ; J8.D25 v1(109.21,66.93) ; J8.J32 v1(102.86,58.04) ; J8.D13 v1(110.48,82.17) ; J8.D19 v1(110.48,75.82) ; J8.G26 v1(105.4,65.66) ; v5(69.63,43.06) 69.48,43.21 C47.2 ; J8.A29 v1(113.02,61.85) ; J8.D28 v1(109.21,63.12) ; J8.B39 v1(111.75,49.15) ; J8.H24 v1(104.13,68.2) ; J8.K33 v1(101.59,56.77) ; J8.C40 v1(110.48,47.88) ; J8.K18 v1(101.59,75.82) ; J8.A20 v1(113.02,73.28) ; J8.B26 v1(111.75,65.66) ; J8.C16 v1(111.75,78.36) J8.C17 ; J8.B22 v1(111.75,70.74) ; J8.D2 v1(109.21,97.41) ; v5(69.63,44.43) 69.61,44.46 C61.2 ; J8.F18 v1(106.67,75.82) ; J8.G20 v1(105.4,73.28) ; J8.C8 v1(111.75,88.52) ; J8.G14 v1(105.4,80.9) ; J8.E17 v1(107.94,78.36) ; J8.D10 v1(110.48,85.98) ; J8.E32 v1(107.94,58.04) ; J8.F21 v1(106.67,72.01) ; J8.H9 v1(104.13,88.52) ; J8.E5 v1(107.94,92.33) ; J8.K39 v1(101.59,49.15) ; J8.B30 v1(111.75,60.58) ; J8.B23 v1(111.75,69.47) ; J8.F12 v1(107.94,83.44) ; J8.H21 v1(104.13,72.01) ; J8.A4 v1(113.02,93.6) ; J8.J29 v1(102.86,61.85) ; J8.D22 v1(109.21,70.74) ; J8.J5 v1(102.86,92.33) ; J8.J17 v1(102.86,78.36) ; J8.K6 v1(101.59,92.33) ; J8.K3 v1(101.59,96.14) ; J8.C12 v1(110.48,84.71) ; J8.K27 v1(101.59,64.39) ; J8.C29 v1(110.48,61.85) ; J8.H27 v1(104.13,64.39) ; J8.B18 v1(111.75,75.82) ; v1(105.4,94.87) J8.G4 J8.G5 ; J8.E29 v1(107.94,61.85) ; J8.A17 v1(113.02,78.36) ; J8.B3 v1(111.75,96.14) ; J8.C24 v1(110.48,68.2) ; J8.E40 v1(107.94,47.88) ; J8.G38 v1(105.4,50.42) ; J8.K15 v1(101.59,80.9) ; J8.K24 v1(101.59,68.2) ; J8.A28 v1(113.02,63.12) ; J8.E38 v1(109.21,51.69) ; J8.D16 v1(110.48,78.36) ; J8.A21 v1(113.02,72.01) ; J8.J8 v1(102.86,88.52) ; J8.F36 v1(106.67,52.96) ; J8.G11 v1(105.4,84.71) ; J8.C38 v1(111.75,51.69) ; J8.H33 v1(104.13,56.77)
  BOTTOM w0.559: 75.08,12.85 C133.2 75.08,14.06 ; 75.08,12.85 v2(76.07,12.85) ; 75.08,12.85 v2(74.09,12.85) ; 94.46,27.17 C146.2 94.46,25.95 ; 94.46,27.17 v2(95.45,27.17) ; 94.46,27.17 v2(93.47,27.17) ; 9.16,60.76 C126.2 7.95,60.76 ; 9.16,60.76 v2(9.16,61.75) ; 9.16,60.76 v2(9.16,59.77) ; 85.66,16.04 C136.2 85.66,14.83 ; 85.66,16.04 v2(84.67,16.04) ; 85.66,16.04 v2(86.65,16.04) ; v2(9.16,47.07) 9.16,48.06 ; 9.16,48.06 C115.2 7.95,48.06 ; 9.16,48.06 v2(9.16,49.05) ; v2(7.95,59.77) 7.95,60.76 ; 7.95,60.76 v2(7.95,61.75) ; v2(47.18,103.87) 48.17,103.87 ; 48.17,103.87 48.17,102.65 ; 48.17,103.87 v2(49.16,103.87) ; 75.08,14.06 v2(74.09,14.06) ; 75.08,14.06 v2(76.07,14.06) ; v2(86.65,14.83) 85.66,14.83 ; 85.66,14.83 v2(84.67,14.83) ; v2(93.47,25.95) 94.46,25.95 ; 94.46,25.95 v2(95.45,25.95) ; 7.95,48.06 v2(7.95,47.07) ; 7.95,48.06 7.95,49.05 ; v2(59.83,102.65) 58.84,102.65 ; 58.84,102.65 v2(57.85,102.65) ; 58.84,102.65 58.84,103.87 ; v2(59.83,103.87) 58.84,103.87 ; 58.84,103.87 v2(57.85,103.87) ; 48.17,102.65 v2(47.18,102.65) ; 48.17,102.65 v2(49.16,102.65)
  vias: v1(5.66,79.6) v1(5.79,77.6) v1(7.09,81.05) v1(7.14,76.05) v1(8,82.03) v1(8,75.18) v1(8.79,82.19) v1(8.84,75.08) v1(9.65,78.99) v1(9.65,78.22) v1(10.11,80.77) v1(10.16,76.4) v1(15.88,78.61) v1(16.81,78.61) v1(27.23,78.87) v1(27.25,78.38) v1(28.68,78.84) v1(28.7,78.36) v1(30.05,78.84) v1(30.07,78.36) v1(31.5,78.87) v1(31.52,78.38) v1(32.97,78.87) v1(32.99,78.38) v1(34.44,78.87) v1(34.47,78.38) v1(35.54,97.34) v1(35.71,78.84) v1(35.74,78.36) v1(36.21,90.4) v1(36.92,92.97) v1(36.93,78.59) v1(40.05,46.21) v1(46.05,75.08) v1(47.29,41.25) v1(47.5,85.72) v1(47.5,84.96) v1(47.83,72.28) v1(48.01,85.34) v1(48.51,85.72) v1(48.51,84.96) v1(49.38,94.74) v1(49.53,93.47) v1(49.53,89.03) v1(50.16,73.25) v1(50.29,86.74) v1(50.32,71.78) v1(51.18,75.11) v1(51.38,73.25) v1(51.56,85.22) v1(51.66,68.61) v1(52.07,93.6) v1(52.07,91.06) v1(52.07,87) v1(52.15,65.56) v1(52.24,75.11) v1(52.35,73.25) v1(52.5,99.03) v1(52.6,69.55) v1(52.75,46.21) v1(53.24,75.11) v1(53.26,67.51) v1(53.37,73.28) v1(53.47,94.74) v1(53.47,92.84) v1(53.47,89.15) v1(53.54,70.48) v1(54.1,87.76) v1(54.53,73.28) v1(54.56,75.11) v1(54.98,99.03) v1(55.11,72.04) v1(55.24,90.81) v1(55.29,40.28) v1(55.83,73.28) v1(55.85,75.11) v1(56.29,94.77) v1(56.26,89.92) v1(56.77,92.84) v1(56.85,73.28) v1(56.9,75.11) v1(57.02,81.92) v1(57.02,80.9) v1(57.4,81.41) v1(57.4,76.61) v1(57.78,81.92) v1(57.78,80.9) v1(57.89,75.08) v1(57.86,73.28) v1(58.29,94.74) v1(58.42,91.95) v1(58.55,83.69) v1(58.67,88.27) v1(58.67,76.61) v1(58.83,75.11) v1(58.88,78.51) v1(59.13,73.28) v1(59.44,85.98) v1(59.44,80.52) v1(59.94,76.61) v1(60.07,82.68) v1(60.15,78.51) v1(60.1,75.11) v1(60.33,91.95) v1(60.4,73.28) v1(60.58,89.28) v1(61.21,76.61) v1(61.34,87.12) v1(61.42,78.51) v1(61.37,75.11) v1(61.72,85.34) v1(61.67,73.28) v1(62.48,76.61) v1(62.64,75.11) v1(62.69,78.51) v1(62.94,73.28) v1(62.99,89.03) v1(63.5,92.71) v1(63.5,87) v1(63.65,93.98) v1(63.8,95.25) v1(63.75,76.61) v1(63.91,75.11) v1(63.96,78.51) v1(64.21,73.28) v1(65.02,76.61) v1(65.15,90.68) v1(65.23,78.51) v1(65.18,75.11) v1(65.41,88.9) v1(65.48,73.28) v1(65.53,13.16) v1(66.29,76.48) v1(66.42,78.71) v1(66.45,75.11) v1(66.75,73.28) v1(67.56,76.61) v1(67.72,75.11) v1(67.77,78.51) v1(68.02,73.28) v1(68.15,55.19) v1(68.33,90.68) v1(68.33,88.77) v1(68.3,56.46) v1(68.63,54) v1(68.83,76.61) v1(69.04,78.51) v1(68.99,75.11) v1(69.29,73.28) v1(69.39,57.18) v1(69.62,53.62) v1(69.98,55.37) v1(70.1,76.61) v1(70.31,78.51) v1(70.26,75.11) v1(70.56,73.28) v1(70.66,59.72) v1(70.66,58.45) v1(70.66,57.18) v1(70.99,60.86) v1(70.97,52.22) v1(71.09,51.31) v1(71.32,55.37) v1(71.37,76.61) v1(71.53,75.11) v1(71.58,78.51) v1(71.63,73.28) v1(71.93,61.8) v1(72.19,55.98) v1(72.64,78.54) v1(72.64,76.66) v1(72.64,75.08) v1(72.57,73.28) v1(72.87,62.74) v1(72.87,60.12) v1(72.95,54.23) v1(73.08,51.94) v1(73.71,75.11) v1(73.71,73.25) v1(73.84,76.66) v1(73.81,63.68) v1(73.81,61.06) v1(73.91,78.51) v1(74.07,57.81) v1(74.07,56.54) v1(74.4,59.03) v1(74.55,55.42) v1(74.78,75.11) v1(74.75,64.62) v1(74.75,62) v1(74.98,73.25) v1(74.96,51.61) v1(75.11,78.51) v1(75.06,76.68) v1(75.34,59.97) v1(75.26,52.58) v1(75.54,57.81) v1(75.54,56.54) v1(75.54,55.27) v1(75.56,59.16) v1(75.69,65.56) v1(75.69,62.94) v1(76.05,75.11) v1(76.25,73.25) v1(76.28,60.91) v1(76.38,76.68) v1(76.45,78.51) v1(76.63,66.5) v1(76.63,63.88) v1(77.22,61.85) v1(77.32,75.11) v1(77.44,58.55) v1(77.44,57.43) v1(77.44,56.16) v1(77.44,54.89) v1(77.52,73.25) v1(77.55,59.44) v1(77.57,67.44) v1(77.57,64.82) v1(77.57,52.12) v1(77.9,76.66) v1(78,78.51) v1(78.16,62.79) v1(78.51,68.38) v1(78.51,65.76) v1(78.59,75.11) v1(78.61,60.63) v1(78.79,73.25) v1(79.1,78.51) v1(79.07,76.68) v1(79.1,63.73) v1(79.45,69.32) v1(79.45,66.7) v1(79.55,61.57) v1(79.86,75.11) v1(80.04,64.67) v1(80.06,73.25) v1(80.09,47) v1(80.19,78.51) v1(80.16,76.66) v1(80.39,70.26) v1(80.39,67.64) v1(80.49,62.51) v1(81.04,75.62) v1(80.98,65.61) v1(81.28,78.51) v1(81.28,76.68) v1(81.33,73.25) v1(81.33,71.2) v1(81.33,68.58) v1(81.43,63.45) v1(81.92,66.55) v1(81.98,76.56) v1(82.14,79.38) v1(82.27,74.19) v1(82.27,72.14) v1(82.27,69.52) v1(82.37,64.39) v1(82.68,47.25) v1(82.92,77.5) v1(82.85,67.49) v1(83.08,80.31) v1(83.21,75.13) v1(83.21,73.08) v1(83.21,70.46) v1(83.31,65.33) v1(83.79,68.43) v1(83.86,78.44) v1(84.02,81.25) v1(84.15,76.07) v1(84.15,74.02) v1(84.15,71.4) v1(84.25,66.27) v1(84.73,69.37) v1(84.8,79.38) v1(84.96,82.19) v1(85.09,77.01) v1(85.09,74.96) v1(85.09,72.34) v1(85.19,67.21) v1(85.74,80.31) v1(85.67,70.31) v1(85.9,83.13) v1(86.03,77.95) v1(86.03,75.9) v1(86.03,73.28) v1(86.13,68.15) v1(86.61,71.25) v1(86.68,81.25) v1(86.97,84.18) v1(86.97,78.89) v1(86.97,76.83) v1(86.97,74.22) v1(87.07,69.09) v1(87.62,82.19) v1(87.55,72.19) v1(87.69,23.79) v1(87.76,85.01) v1(87.91,79.83) v1(87.91,77.77) v1(87.91,75.16) v1(88.01,70.03) v1(88.49,73.13) v1(88.56,83.13) v1(88.7,85.95) v1(88.85,80.77) v1(88.85,78.71) v1(88.85,76.1) v1(88.95,70.97) v1(89.31,83.9) v1(89.43,74.07) v1(89.71,86.94) v1(89.79,81.71) v1(89.79,79.65) v1(89.79,77.04) v1(89.89,71.91) v1(90.04,84.63) v1(90.14,33.59) v1(90.37,75.01) v1(90.58,87.78) v1(90.73,82.65) v1(90.73,80.59) v1(90.73,77.98) v1(90.83,72.85) v1(90.98,85.55) v1(91.47,88.67) v1(91.92,86.49) v1(92.13,83.13) v1(92.13,80.75) v1(92.13,78.87) v1(92.23,84.2) v1(92.15,75.54) v1(92.68,89.92) v1(92.74,87.38) v1(92.81,78.05) v1(92.84,76.25) v1(92.81,73.74) v1(92.98,86.28) v1(93.09,84.43) v1(93.45,90.68) v1(93.4,83.13) v1(93.4,80.75) v1(93.4,78.87) v1(93.47,88.16) v1(93.57,75.54) v1(93.75,73.74) v1(93.98,66.93) v1(94.08,78.05) v1(94.11,76.25) v1(94.26,87.27) v1(94.25,86.28) v1(94.31,84.4) v1(94.39,89.03) v1(94.67,83.13) v1(94.67,80.75) v1(94.67,78.87) v1(94.69,75.54) v1(94.82,73.71) v1(95.25,68.2) v1(95.35,78.05) v1(95.38,76.25) v1(95.53,88.65) v1(95.53,87.83) v1(95.5,87.05) v1(95.52,86.28) v1(95.52,84.38) v1(95.52,83.77) v1(95.94,83.13) v1(95.94,80.75) v1(95.94,78.87) v1(95.94,73.71) v1(95.91,54.86) v1(95.91,53.59) v1(95.91,52.32) v1(95.91,51.05) v1(95.96,75.54) v1(95.95,60.73) v1(96.09,93.32) v1(97.23,94.39) v1(97.38,92) v1(98.12,92.53) v1(98.5,94.39) v1(99.39,92.53) v1(99.39,89.99) v1(100.84,94.39) v1(101.45,82.85) v1(101.59,98.68) v1(101.59,94.87) v1(101.59,87.25) v1(101.59,78.36) v1(101.59,73.28) v1(101.59,66.93) v1(101.59,63.12) v1(101.59,61.85) v1(101.59,59.31) v1(101.59,58.04) v1(101.59,55.5) v1(102.86,97.41) v1(102.86,96.14) v1(102.86,94.87) v1(102.86,87.25) v1(102.86,75.82) v1(102.86,72.01) v1(102.86,70.74) v1(102.86,68.2) v1(102.86,66.93) v1(102.86,64.39) v1(102.86,63.12) v1(102.86,60.58) v1(102.86,59.31) v1(102.86,56.77) v1(102.86,55.5) v1(104.13,98.68) v1(104.13,94.87) v1(104.13,87.25) v1(104.13,78.36) v1(104.13,73.28) v1(104.13,70.74) v1(104.13,69.47) v1(104.13,66.93) v1(104.13,65.66) v1(104.13,63.12) v1(104.13,61.85) v1(104.13,58.04) v1(104.13,55.5) v1(105.4,97.41) v1(105.4,96.14) v1(105.4,75.82) v1(105.4,72.01) v1(105.4,70.74) v1(105.4,64.39) v1(105.4,63.12) v1(105.4,60.58) v1(105.4,59.31) v1(105.4,56.77) v1(105.4,55.5) v1(106.67,94.87) v1(106.67,78.36) v1(106.67,73.28) v1(106.67,70.74) v1(106.67,69.47) v1(106.67,66.93) v1(106.67,65.66) v1(106.67,63.12) v1(106.67,61.85) v1(106.67,59.31) v1(106.67,58.04) v1(106.67,56.77) v1(106.67,55.5) v1(106.67,54.23) v1(106.67,51.69) v1(106.67,50.42) v1(107.94,97.41) v1(107.94,96.14) v1(107.94,80.9) v1(107.94,75.82) v1(107.94,72.01) v1(107.94,70.74) v1(107.94,68.2) v1(107.94,66.93) v1(107.94,64.39) v1(107.94,63.12) v1(107.94,60.58) v1(107.94,59.31) v1(107.94,56.77) v1(107.94,55.5) v1(107.94,54.23) v1(107.94,52.96) v1(107.94,51.69) v1(109.21,88.52) v1(109.21,87.25) v1(109.21,84.71) v1(109.21,83.44) v1(109.21,80.9) v1(109.21,78.36) v1(109.21,75.82) v1(109.21,73.28) v1(109.21,72.01) v1(109.21,69.47) v1(109.21,68.2) v1(109.21,65.66) v1(109.21,64.39) v1(109.21,61.85) v1(109.21,58.04) v1(109.21,56.77) v1(109.21,55.5) v1(109.21,54.23) v1(109.21,52.96) v1(109.21,50.42) v1(109.21,47.88) v1(110.48,97.41) v1(110.48,96.14) v1(110.48,80.9) v1(110.48,70.74) v1(110.48,69.47) v1(110.48,65.66) v1(110.48,64.39) v1(110.48,60.58) v1(110.48,59.31) v1(110.48,56.77) v1(110.48,55.5) v1(110.48,54.23) v1(110.48,51.69) v1(110.48,49.15) v1(111.75,98.68) v1(111.75,84.71) v1(111.75,83.44) v1(111.75,82.17) v1(111.75,73.28) v1(111.75,72.01) v1(111.75,68.2) v1(111.75,66.93) v1(111.75,63.12) v1(111.75,61.85) v1(111.75,58.04) v1(111.75,56.77) v1(111.75,55.5) v1(111.75,54.23) v1(111.75,52.96) v1(111.75,47.88) v1(113.02,97.41) v1(113.02,96.14) v1(113.02,80.9) v1(113.02,70.74) v1(113.02,69.47) v1(113.02,65.66) v1(113.02,64.39) v1(113.02,60.58) v1(113.02,59.31) v1(113.02,56.77) v1(113.02,55.5) v1(113.02,54.23) v1(113.02,52.96) v1(113.02,50.42) v1(113.02,49.15) v1(114.29,75.82) v1(114.29,56.77) v1(114.29,54.23) v1(114.38,95.81) v1(114.38,93.95) v1(114.38,90.09) v1(114.45,86.66) v1(114.76,80.75) v1(115.01,73.33) v1(115.19,85.62) v1(115.19,84.35) v1(115.19,83.08) v1(115.19,81.81) v1(115.49,76.5) v1(115.65,95.81) v1(115.65,93.95) v1(115.65,90.09) v1(115.95,74.27) v1(116.43,77.44) v1(116.71,93.01) v1(116.89,95.43) v1(116.92,89.87) v1(116.89,75.21) v1(117.04,87.12) v1(117.04,85.85) v1(117.04,84.58) v1(117.04,83.31) v1(117.04,82.04) v1(117.04,80.77) v1(117.37,78.38) v1(117.65,92.08) v1(117.83,94.49) v1(117.83,76.15) v1(117.86,88.93) v1(118.31,79.32) v1(118.59,91.14) v1(118.77,93.55) v1(118.8,90.53) v1(118.8,89.26) v1(118.8,87.99) v1(118.77,77.09) v1(119.71,92.61) v1(119.71,78.03) v1(120.65,91.67) v1(120.65,90.4) v1(120.65,89.13) v1(120.65,87.86) v1(120.65,86.59) v1(120.65,85.32) v1(120.65,84.05) v1(120.65,82.78) v1(120.65,81.51) v1(120.65,80.24) v1(120.65,78.97) v2(0.91,64.77) v2(0.91,59.69) v2(0.91,54.61) v2(0.91,49.53) v2(0.91,44.45) v2(0.91,39.37) v2(0.91,34.29) v2(0.91,29.21) v2(0.91,24.13) v2(1.01,89.8) v2(1.01,88.36) v2(1.01,81.29) v2(1.01,79.85) v2(0.96,78.55) v2(1.01,77.36) v2(1.01,75.92) v2(1.01,68.85) v2(1.01,67.41) v2(0.97,62.08) v2(0.97,57) v2(0.97,51.92) v2(0.97,46.84) v2(0.97,41.76) v2(0.97,36.68) v2(0.97,31.6) v2(0.97,26.52) v2(1.32,105.26) v2(1.32,100.18) v2(1.32,95.1) v2(1.37,102.67) v2(1.37,97.59) v2(1.37,92.51) v2(1.52,73.48) v2(1.62,85.91) v2(1.6,71.28) v2(1.74,89.8) v2(1.74,88.36) v2(1.69,83.71) v2(1.71,81.29) v2(1.71,79.85) v2(1.77,77.38) v2(1.77,75.94) v2(1.79,68.87) v2(1.79,67.43) v2(2.08,106.05) v2(2.2,56.34) v2(2.2,43.64) v2(3.29,85.93) v2(3.37,83.73) v2(3.41,73.48) v2(3.49,71.28) v2(3.48,64.06) v2(3.45,24.13) v2(3.61,59.72) v2(3.84,51.64) v2(3.84,46.58) v2(4.13,89.8) v2(4.13,88.36) v2(4.1,81.29) v2(4.1,79.85) v2(4.15,77.38) v2(4.15,75.94) v2(4.18,68.87) v2(4.18,67.43) v2(4.62,106.05) v2(5.12,89.8) v2(5.12,88.36) v2(5.06,85.93) v2(5.14,83.73) v2(5.13,82.56) v2(5.12,81.29) v2(5.12,79.85) v2(5.12,77.36) v2(5.12,75.92) v2(5.1,74.67) v2(5.1,73.49) v2(5.12,68.85) v2(5.12,67.41) v2(5.18,71.29) v2(5.42,78.61) v2(5.99,95.25) v2(5.99,34.29) v2(5.99,29.21) v2(5.99,24.13) v2(6.3,90.17) v2(6.45,78.99) v2(6.5,78.13) v2(6.68,85.37) v2(6.72,71.77) v2(7,55.74) v2(7,54.5) v2(7,53.25) v2(7,43.04) v2(7,41.8) v2(7,40.55) v2(7.16,106.05) v2(7.16,38.96) v2(7.32,83.72) v2(7.32,82.58) v2(7.3,74.72) v2(7.3,73.52) v2(7.41,50.77) v2(7.41,38.07) v2(7.98,78.89) v2(8,78.33) v2(8.04,55.74) v2(8.04,53.25) v2(8.04,43.04) v2(8.04,40.55) v2(8.53,24.13) v2(8.59,67.41) v2(8.58,58.8) v2(8.58,57.59) v2(8.58,46.1) v2(8.58,44.89) v2(9.08,55.74) v2(9.08,54.5) v2(9.08,53.25) v2(9.08,43.04) v2(9.08,41.8) v2(9.08,40.55) v2(9.22,106.12) v2(9.29,58.8) v2(9.29,57.59) v2(9.29,46.1) v2(9.29,44.89) v2(9.58,74.52) v2(9.65,82.7) v2(9.7,63.17) v2(9.7,50.47) v2(10.92,74.45) v2(10.97,82.78) v2(11.05,80.86) v2(11.05,76.35) v2(11.07,100.33) v2(11.07,95.25) v2(11.07,90.17) v2(11.07,85.08) v2(11.07,69.85) v2(11.07,64.77) v2(11.13,54.31) v2(11.13,41.61) v2(11.07,39.37) v2(11.07,24.13) v2(11.15,58.84) v2(11.15,58.14) v2(11.15,46.14) v2(11.15,45.44) v2(11.4,34.34) v2(11.4,29.26) v2(11.76,106.12) v2(12.06,25.4) v2(12.32,24.26) v2(12.37,58.84) v2(12.37,58.14) v2(12.37,46.14) v2(12.37,45.44) v2(12.45,26.92) v2(12.67,53.75) v2(12.93,82.78) v2(12.95,74.47) v2(13.03,27.25) v2(13.03,24.84) v2(13.07,80.83) v2(13.07,76.41) v2(13.59,27.69) v2(13.95,58.72) v2(13.95,57.75) v2(13.95,46.02) v2(13.95,45.05) v2(13.97,25.27) v2(13.97,24.26) v2(14.3,106.12) v2(14.53,82.75) v2(14.53,74.45) v2(14.61,76.4) v2(14.66,80.85) v2(14.66,58.72) v2(14.66,57.75) v2(14.66,46.02) v2(14.66,45.05) v2(16.13,82.8) v2(16.13,80.86) v2(16.12,76.37) v2(16.15,100.33) v2(16.15,95.25) v2(16.15,90.17) v2(16.15,85.09) v2(16.15,69.85) v2(16.15,64.77) v2(16.15,39.37) v2(16.15,34.29) v2(16.15,29.21) v2(16.15,24.13) v2(16.28,74.45) v2(16.84,106.12) v2(17.2,57.66) v2(17.2,53.75) v2(17.37,48.82) v2(17.37,43.74) v2(17.74,76.38) v2(17.75,82.75) v2(17.78,80.86) v2(17.81,74.45) v2(19.38,106.12) v2(20.19,61.42) v2(20.32,80.54) v2(20.32,76.63) v2(20.4,74.47) v2(20.59,82.76) v2(21.23,100.33) v2(21.23,95.25) v2(21.23,90.17) v2(21.23,85.09) v2(21.59,80.86) v2(21.59,76.35) v2(21.84,69.85) v2(21.84,64.77) v2(21.84,54.39) v2(21.84,44.45) v2(21.84,39.37) v2(21.84,34.29) v2(21.92,106.12) v2(22.86,80.86) v2(22.86,76.35) v2(22.99,82.78) v2(23.01,74.42) v2(23.24,31.22) v2(23.75,71.4) v2(23.75,66.32) v2(24.01,106.08) v2(23.98,24.32) v2(24.41,74.9) v2(24.49,42.95) v2(24.49,37.87) v2(24.59,74.22) v2(24.64,57.56) v2(24.64,52.48) v2(24.8,81.98) v2(25.43,85.09) v2(25.45,80.99) v2(25.45,76.22) v2(25.65,83.01) v2(26.31,100.33) v2(26.31,95.25) v2(26.31,90.17) v2(26.55,106.08) v2(26.66,34.29) v2(26.82,81) v2(26.82,76.23) v2(26.8,72.26) v2(26.8,68.07) v2(26.93,66.12) v2(27.3,69.85) v2(27.3,59.34) v2(27.3,54.61) v2(27.3,49.53) v2(27.3,44.45) v2(27.3,39.37) v2(27.33,32.61) v2(27.33,30.07) v2(27.41,83.01) v2(28.08,24.32) v2(28.42,81) v2(28.5,76.23) v2(28.55,74.22) v2(28.47,43.79) v2(28.47,41.25) v2(28.57,55.88) v2(28.57,50.42) v2(28.6,38.33) v2(28.6,35.79) v2(29.09,106.08) v2(29.16,82.98) v2(29.59,91.7) v2(29.95,81.03) v2(30.02,76.25) v2(30.02,74.22) v2(30.33,35.71) v2(30.45,43.43) v2(30.45,38.35) v2(30.51,31.45) v2(30.54,24.32) v2(30.66,62.97) v2(31.01,83.01) v2(30.96,52.81) v2(30.96,47.73) v2(31.08,100.47) v2(31.34,81.03) v2(31.43,93.36) v2(31.42,76.25) v2(31.37,64.8) v2(31.37,59.84) v2(31.63,106.08) v2(31.69,91.44) v2(31.75,54.61) v2(31.75,49.53) v2(31.88,89.69) v2(32.41,83.01) v2(32.5,71.72) v2(32.74,81) v2(32.82,76.23) v2(32.87,94.75) v2(32.97,74.22) v2(33.08,24.32) v2(33.19,92.85) v2(33.17,85.09) v2(33.17,64.77) v2(33.17,44.45) v2(33.17,39.37) v2(33.2,34.29) v2(33.35,91.19) v2(33.72,106.01) v2(33.91,82.93) v2(34.06,90.07) v2(34.06,59.74) v2(34.37,74.7) v2(34.46,96.04) v2(34.54,94.32) v2(34.59,85.09) v2(34.59,54.61) v2(34.59,49.53) v2(34.72,82.14) v2(34.75,81) v2(34.75,22.94) v2(34.75,20.4) v2(34.75,17.86) v2(34.75,15.32) v2(34.75,12.78) v2(34.75,10.24) v2(34.75,7.7) v2(34.75,5.16) v2(34.75,2.62) v2(34.78,92.75) v2(34.82,76.23) v2(35.08,25.81) v2(35.39,91.35) v2(35.43,4.05) v2(35.43,1.66) v2(35.45,5.12) v2(35.45,0.98) v2(35.83,100.36) v2(36.02,85.09) v2(35.97,74.22) v2(36.04,64.7) v2(36.02,49.53) v2(36.02,44.45) v2(36.02,39.37) v2(35.99,34.29) v2(36.07,81) v2(36.14,76.23) v2(36.12,22.83) v2(36.2,67.18) v2(36.26,106.01) v2(36.27,31.55) v2(36.47,20.7) v2(36.5,18.8) v2(36.48,16.51) v2(36.48,13.97) v2(36.83,28.37) v2(36.83,9.53) v2(36.91,59.74) v2(36.89,5.12) v2(36.87,4.05) v2(36.87,1.66) v2(36.89,0.98) v2(37.35,43.83) v2(37.32,42.51) v2(37.41,80.99) v2(37.41,76.22) v2(37.41,54.71) v2(37.38,50.13) v2(37.41,48.87) v2(37.41,47.6) v2(37.41,46.33) v2(37.38,45.12) v2(38.1,24.99) v2(38.43,69.88) v2(38.48,88.29) v2(38.63,46.99) v2(38.63,45.49) v2(38.68,80.99) v2(38.68,76.22) v2(38.73,50.63) v2(38.8,106.01) v2(38.81,16.05) v2(38.81,14.78) v2(38.89,38.2) v2(38.89,36.93) v2(38.89,35.66) v2(38.89,34.39) v2(38.89,33.12) v2(38.89,31.85) v2(38.89,30.58) v2(38.94,29.24) v2(38.94,26.11) v2(38.86,24.13) v2(38.94,22.02) v2(38.89,20.37) v2(38.91,18.97) v2(38.94,17.55) v2(38.89,13.44) v2(38.91,11.3) v2(38.89,10.01) v2(38.94,8.64) v2(38.94,7.65) v2(39.12,44.45) v2(39.12,41.25) v2(39.12,39.98) v2(39.22,48.08) v2(39.27,49.63) v2(39.34,42.95) v2(39.34,5.44) v2(39.32,4.09) v2(39.34,2.51) v2(39.34,1.02) v2(39.55,51.36) v2(39.83,80.86) v2(39.83,76.35) v2(39.84,64.76) v2(40.23,51.97) v2(40.74,42.93) v2(40.83,53.2) v2(40.97,41.25) v2(40.97,39.98) v2(41.1,80.86) v2(41.1,76.35) v2(41.15,24.77) v2(41.12,22) v2(41.1,18.92) v2(41.12,17.5) v2(41.12,16.05) v2(41.12,14.78) v2(41.15,13.46) v2(41.15,10.03) v2(41.15,7.62) v2(41.25,92.61) v2(41.22,57.78) v2(41.2,38.2) v2(41.2,36.93) v2(41.2,34.39) v2(41.2,33.12) v2(41.2,31.85) v2(41.2,30.58) v2(41.2,29.31) v2(41.2,27.81) v2(41.2,20.37) v2(41.17,11.33) v2(41.17,8.64) v2(41.34,106.01) v2(41.32,50.57) v2(41.53,5.44) v2(41.5,4.09) v2(41.53,2.51) v2(41.53,1.02) v2(41.69,54.02) v2(41.66,41.25) v2(41.66,39.98) v2(41.91,42.95) v2(42.04,36.58) v2(42.29,76.61) v2(42.29,51.87) v2(42.34,46.3) v2(42.39,80.8) v2(42.52,99.21) v2(42.55,58.19) v2(42.57,68.22) v2(42.6,54.94) v2(42.59,40.28) v2(42.82,18.39) v2(42.8,13.72) v2(43.15,52.73) v2(43.18,51.08) v2(43.26,72.64) v2(43.28,42.95) v2(43.33,36.55) v2(43.41,55.87) v2(43.38,49.68) v2(43.43,48.13) v2(43.51,44.45) v2(43.52,41.25) v2(43.52,39.98) v2(43.59,75.36) v2(43.83,103.87) v2(43.83,102.9) v2(44.04,53.62) v2(44,46.99) v2(44,45.49) v2(43.96,5.12) v2(43.96,4.1) v2(43.96,1.71) v2(43.96,0.98) v2(44.07,10.59) v2(44.07,7.87) v2(44.23,56.68) v2(44.26,50.58) v2(44.54,103.87) v2(44.54,102.9) v2(44.5,34.29) v2(44.63,23.6) v2(44.68,84.18) v2(44.68,82.32) v2(44.73,60.56) v2(44.68,32.11) v2(44.68,27.03) v2(44.78,61.49) v2(44.77,59.54) v2(44.81,58.66) v2(44.84,57.66) v2(44.93,54.56) v2(44.98,62.41) v2(45.09,20.45) v2(45.09,15.37) v2(45.22,48.87) v2(45.22,47.6) v2(45.22,46.33) v2(45.22,45.06) v2(45.22,43.79) v2(45.22,42.52) v2(45.34,63.55) v2(45.32,50.03) v2(45.36,39.22) v2(45.4,5.12) v2(45.4,4.1) v2(45.4,1.71) v2(45.4,0.98) v2(45.64,36.55) v2(45.7,71.36) v2(45.7,70.44) v2(45.72,69.09) v2(45.75,67.89) v2(45.77,88.29) v2(45.77,73.08) v2(45.77,66.37) v2(45.77,65.1) v2(45.94,102.29) v2(45.87,92.46) v2(45.95,55.5) v2(46.94,62.31) v2(46.91,54.56) v2(46.91,4.14) v2(46.86,1.04) v2(46.96,57.53) v2(46.99,36.45) v2(47.07,61.44) v2(47.09,60.58) v2(47.12,58.57) v2(47.22,59.46) v2(47.7,63.12) v2(47.7,56.57) v2(47.75,68.4) v2(47.75,66.65) v2(47.75,65.1) v2(47.75,64.06) v2(47.88,53.52) v2(47.9,13) v2(47.96,70.34) v2(47.96,51.05) v2(47.96,45.97) v2(48.03,35.92) v2(48.03,34.26) v2(48.23,69.16) v2(48.23,67.51) v2(48.23,66.09) v2(48.18,60.58) v2(48.18,58.62) v2(48.15,5.12) v2(48.18,4.1) v2(48.18,1.71) v2(48.15,0.98) v2(48.26,61.42) v2(48.41,62.28) v2(48.36,57.51) v2(48.54,31.22) v2(48.54,26.14) v2(48.62,56.01) v2(48.62,22.02) v2(48.62,16.94) v2(48.56,10.59) v2(48.64,7.9) v2(48.77,64.85) v2(48.77,63.3) v2(48.82,52.58) v2(49.33,55.3) v2(49.35,39.12) v2(49.59,5.12) v2(49.62,4.1) v2(49.62,1.71) v2(49.59,0.98) v2(49.76,51.64) v2(50.14,69.11) v2(50.14,67.51) v2(50.11,66.17) v2(50.05,49.88) v2(50.09,48.58) v2(50.11,47.6) v2(50.11,46.33) v2(50.11,45.06) v2(50.11,43.79) v2(50.11,42.52) v2(50.24,62.18) v2(50.24,54.38) v2(50.34,35.92) v2(50.34,34.26) v2(50.53,61.44) v2(50.5,60.56) v2(50.61,65.15) v2(50.62,63.98) v2(50.62,63.04) v2(50.61,59.09) v2(50.64,58.1) v2(50.85,50.55) v2(51.28,53.44) v2(51.33,46.99) v2(51.33,45.49) v2(51.59,38.2) v2(51.59,36.93) v2(51.56,35.81) v2(51.59,34.26) v2(51.59,33.12) v2(51.59,31.85) v2(51.59,30.58) v2(51.59,29.31) v2(51.59,27.81) v2(51.59,26.34) v2(51.56,24.99) v2(51.61,23.44) v2(51.59,21.44) v2(51.59,20.17) v2(51.61,18.95) v2(51.61,16.48) v2(51.61,15.21) v2(51.64,13.84) v2(51.61,12.57) v2(51.64,11.2) v2(51.61,10.03) v2(51.61,8.64) v2(51.61,7.59) v2(51.66,17.55) v2(51.79,44.45) v2(51.82,41.25) v2(51.82,39.98) v2(51.94,57.81) v2(51.94,49.48) v2(51.89,48.16) v2(51.97,55.8) v2(52.01,52.45) v2(52.02,5.56) v2(52.02,4.32) v2(52.02,2.77) v2(52.02,0.89) v2(52.07,42.9) v2(52.65,51.64) v2(52.98,55.96) v2(53.21,57.81) v2(53.42,42.93) v2(53.67,41.25) v2(53.67,39.98) v2(53.85,17.5) v2(53.85,16.48) v2(53.85,15.21) v2(53.85,13.82) v2(53.85,11.18) v2(53.82,10.01) v2(53.85,8.64) v2(53.85,7.65) v2(53.87,54.09) v2(53.92,50.61) v2(53.9,38.2) v2(53.9,36.93) v2(53.9,34.26) v2(53.9,33.12) v2(53.9,31.85) v2(53.9,30.58) v2(53.9,29.31) v2(53.9,27.81) v2(53.9,26.34) v2(53.87,24.99) v2(53.9,21.44) v2(53.9,20.17) v2(53.87,18.92) v2(53.92,12.57) v2(53.98,35.81) v2(53.97,23.52) v2(54.2,5.56) v2(54.2,4.32) v2(54.2,2.77) v2(54.2,0.89) v2(54.33,57.51) v2(54.36,41.25) v2(54.36,39.98) v2(54.5,103.87) v2(54.5,102.9) v2(54.56,53.24) v2(54.58,42.9) v2(54.69,64.77) v2(54.71,61.65) v2(54.93,55.19) v2(55.02,78.66) v2(54.99,56.31) v2(55.02,46.23) v2(55.14,83.24) v2(55.07,52.32) v2(55.21,103.87) v2(55.21,102.9) v2(55.27,35.79) v2(55.58,34.34) v2(55.83,51.46) v2(55.96,42.9) v2(56.08,78.84) v2(56.19,45.49) v2(56.21,44.45) v2(56.22,41.25) v2(56.22,39.98) v2(56.26,48.13) v2(56.52,7.87) v2(56.61,102.29) v2(56.63,4.03) v2(56.63,1.64) v2(56.71,50.62) v2(56.66,5.12) v2(56.66,0.98) v2(56.79,31.39) v2(56.87,26.24) v2(56.87,21.16) v2(57.05,16.56) v2(57.2,13.21) v2(57.3,56.49) v2(57.28,35.94) v2(57.28,34.29) v2(57.54,46.9) v2(57.6,49.68) v2(57.75,11) v2(57.92,43.79) v2(57.92,42.52) v2(58.1,5.12) v2(58.08,4.03) v2(58.08,1.64) v2(58.1,0.98) v2(58.47,45.96) v2(58.65,48.62) v2(58.57,35.92) v2(58.57,34.26) v2(58.9,53.04) v2(59.31,42.14) v2(59.41,45.02) v2(59.59,1.07) v2(59.74,34.29) v2(59.82,47.42) v2(59.77,39.37) v2(59.82,35.81) v2(60.25,41.2) v2(60.35,44.08) v2(60.44,34.05) v2(60.43,7.85) v2(60.57,61.65) v2(60.74,70.89) v2(60.74,65.81) v2(60.68,4.09) v2(61.04,26.19) v2(61.17,56.49) v2(61.19,40.26) v2(61.29,43.14) v2(61.34,33.11) v2(61.59,35.19) v2(61.95,23.88) v2(62,1.07) v2(62.05,100.58) v2(62.23,42.2) v2(62.31,97.33) v2(62.26,45.09) v2(62.48,34.25) v2(62.59,39.93) v2(62.59,29.41) v2(62.81,35.92) v2(63.2,44.15) v2(63.27,15.16) v2(63.47,42.04) v2(63.53,22.5) v2(63.75,5.12) v2(63.77,4.18) v2(63.77,1.79) v2(63.75,0.98) v2(64.24,48.79) v2(64.24,46.94) v2(64.26,32.64) v2(64.87,26.14) v2(65.24,106.38) v2(65.24,105.16) v2(65.2,61.62) v2(65.2,56.54) v2(65.23,50.11) v2(65.19,5.12) v2(65.21,4.18) v2(65.21,1.79) v2(65.19,0.98) v2(65.28,103.29) v2(65.28,102.59) v2(65.25,52.58) v2(65.37,70.86) v2(65.37,65.78) v2(65.41,44.83) v2(65.41,39.88) v2(65.71,20.24) v2(65.94,106.38) v2(65.94,105.16) v2(65.86,38.38) v2(65.91,18.11) v2(66.29,34.16) v2(66.29,32.64) v2(66.27,6.93) v2(66.36,86.13) v2(66.36,81.05) v2(66.45,2.02) v2(66.49,103.29) v2(66.49,102.59) v2(66.57,36.8) v2(66.6,24.38) v2(66.85,46.88) v2(67.31,15.16) v2(67.31,10.08) v2(67.56,4.19) v2(67.56,2.41) v2(67.56,0.89) v2(67.74,97.35) v2(68.12,40.03) v2(68.34,103.09) v2(68.34,102.04) v2(68.34,101) v2(68.26,5.11) v2(69.22,34.16) v2(69.22,32.64) v2(69.24,22.33) v2(69.24,20.42) v2(69.24,19.15) v2(69.24,16.87) v2(69.24,15.6) v2(69.24,13.44) v2(69.24,12.17) v2(69.24,10.26) v2(69.24,8.99) v2(69.24,7.34) v2(69.24,6.07) v2(69.42,95.99) v2(69.37,26.01) v2(69.37,24.74) v2(69.58,103.09) v2(69.58,101) v2(69.77,105.13) v2(69.85,2.41) v2(69.85,1.02) v2(70.03,3.57) v2(70.28,61.49) v2(70.46,70.82) v2(70.45,65.78) v2(70.46,36.78) v2(70.83,103.09) v2(70.83,102.04) v2(70.83,101) v2(70.76,53.54) v2(70.87,106.22) v2(70.93,4.47) v2(70.99,86.1) v2(70.99,81.02) v2(71.53,2.02) v2(71.55,22.33) v2(71.55,20.42) v2(71.55,19.15) v2(71.55,16.87) v2(71.55,15.6) v2(71.55,13.44) v2(71.55,12.17) v2(71.55,10.26) v2(71.55,8.99) v2(71.55,7.34) v2(71.55,6.07) v2(71.68,26.01) v2(71.68,24.74) v2(71.86,39.05) v2(72.2,4.15) v2(72.2,1.77) v2(72.26,5.12) v2(72.26,0.98) v2(72.42,101.16) v2(72.47,34.09) v2(72.47,32.13) v2(72.47,28.96) v2(72.67,14.6) v2(73.01,28.03) v2(73.03,10.92) v2(73.3,101.41) v2(73.41,106.22) v2(73.38,93.55) v2(73.56,34.09) v2(73.56,32.13) v2(73.56,28.98) v2(73.56,27.03) v2(73.65,4.15) v2(73.65,1.77) v2(73.7,5.12) v2(73.7,0.98) v2(74.17,39.05) v2(74.75,21.49) v2(74.98,36.8) v2(75.01,29.01) v2(75.01,27.05) v2(75.31,70.82) v2(75.26,53.95) v2(75.54,25.98) v2(75.95,106.22) v2(76.1,29.01) v2(76.1,27.05) v2(76.43,91.52) v2(76.39,86.03) v2(76.39,80.95) v2(76.45,5.12) v2(76.5,4.15) v2(76.5,1.77) v2(76.45,0.98) v2(76.83,16) v2(77.02,38.21) v2(77.02,36.87) v2(77.75,53.54) v2(77.89,5.12) v2(77.94,4.15) v2(77.94,1.77) v2(77.89,0.98) v2(78,106.3) v2(78.24,34.71) v2(78.23,33.66) v2(78.71,101.85) v2(78.77,9.88) v2(78.77,8.61) v2(78.89,31.85) v2(78.89,30.58) v2(78.89,28.68) v2(78.89,27.41) v2(78.89,25.12) v2(78.89,23.85) v2(78.89,21.69) v2(78.89,20.42) v2(78.89,18.26) v2(78.89,16.99) v2(78.89,13.82) v2(78.89,12.55) v2(78.89,7.47) v2(78.89,6.2) v2(79.14,4.52) v2(80.04,3.62) v2(80.26,2.41) v2(80.26,0.89) v2(80.54,106.3) v2(81.02,86) v2(81.02,80.92) v2(81.08,9.88) v2(81.08,8.61) v2(81.2,30.58) v2(81.19,28.83) v2(81.19,26.76) v2(81.19,24.69) v2(81.2,21.69) v2(81.2,20.42) v2(81.2,18.26) v2(81.2,16.99) v2(81.2,13.82) v2(81.2,12.55) v2(81.2,7.47) v2(81.2,6.2) v2(81.8,5.03) v2(81.94,39.88) v2(82,28.83) v2(82,26.76) v2(82,24.69) v2(82.55,4.06) v2(82.55,2.41) v2(82.55,1.02) v2(82.73,45.42) v2(82.98,60.3) v2(82.98,55.22) v2(83.08,106.3) v2(83.24,16.58) v2(84.63,43.24) v2(84.63,41.17) v2(84.63,39.1) v2(84.71,102.97) v2(84.93,4.15) v2(84.93,1.77) v2(84.96,5.12) v2(84.96,0.98) v2(85.45,43.24) v2(85.45,41.17) v2(85.45,39.1) v2(85.62,106.3) v2(86.11,85.93) v2(86.16,51.99) v2(86.4,5.12) v2(86.37,4.15) v2(86.37,1.77) v2(86.4,0.98) v2(87.19,99.16) v2(87.19,94.08) v2(87.66,22.91) v2(87.78,19.26) v2(87.78,18.04) v2(87.81,16.17) v2(87.81,15.46) v2(87.9,21.54) v2(87.9,20.83) v2(88.09,35.74) v2(88.16,106.3) v2(88.19,1.02) v2(88.54,66.93) v2(88.54,61.85) v2(88.48,19.26) v2(88.48,18.04) v2(88.85,51.32) v2(88.86,21.54) v2(88.86,20.83) v2(89.02,16.17) v2(89.02,15.46) v2(90.12,30.94) v2(90.12,25.86) v2(90.2,22.91) v2(90.27,9.08) v2(90.64,38.21) v2(90.7,106.3) v2(90.88,15.96) v2(90.88,14.92) v2(90.88,13.88) v2(90.88,1.02) v2(91.82,99.13) v2(91.82,94.05) v2(92.05,27.7) v2(92.12,15.96) v2(92.12,13.88) v2(92.3,18.01) v2(92.53,58.19) v2(92.71,48.06) v2(92.71,42.98) v2(92.8,106.25) v2(92.79,70.99) v2(93.36,15.96) v2(93.36,14.92) v2(93.36,13.88) v2(93.88,1.02) v2(94.95,10.72) v2(95.34,106.25) v2(95.94,67.01) v2(95.86,63.8) v2(95.91,58.17) v2(96.04,49.83) v2(96.34,25.91) v2(96.34,10.29) v2(96.39,40.51) v2(96.44,38.38) v2(96.37,28.32) v2(96.44,7.7) v2(96.37,5.28) v2(96.39,3.48) v2(96.42,1.07) v2(96.47,35.79) v2(96.47,33.43) v2(96.47,30.87) v2(97.69,103.73) v2(97.88,106.25) v2(98.42,44.93) v2(98.42,40.51) v2(98.76,49.76) v2(100.42,106.25) v2(100.41,40.54) v2(102.5,106.19) v2(102.64,40.51) v2(103.21,101.26) v2(105.75,101.26) v2(109.1,106.06) v2(109.27,46.23) v2(109.65,40.36) v2(110.54,106.07) v2(110.72,100.42) v2(112.24,106.02) v2(112.55,40.34) v2(114.18,106.06) v2(115.44,51.75) v2(115.42,42.58) v2(115.37,40.34) v2(115.48,100.56) v2(115.46,91.38) v2(115.5,68.1) v2(115.5,63.02) v2(115.48,56.59) v2(115.48,47.2) v2(116.31,106.06) v2(118.31,40.34) v2(118.52,106.05) v2(120.91,105.82) v2(120.91,103) v2(120.87,100.4) v2(121,98.11) v2(121.05,96.04) v2(121.03,77.34) v2(121.01,65.15) v2(120.98,62.74) v2(121.01,60.07) v2(120.98,57.53) v2(121.01,54.99) v2(121.01,52.48) v2(121.01,49.91) v2(120.98,47.12) v2(121.01,42.11) v2(121.03,40.31) v2(121.08,75.21) v2(121.11,72.62) v2(121.11,70.26) v2(121.11,67.7) v2(121.08,44.53) v2(121.18,93.75) v4(47.24,79.6) v4(47.24,78.6) v4(47.24,77.61) v4(47.24,76.61) v4(48.24,79.6) v4(48.24,78.6) v4(48.24,77.61) v4(48.24,76.61) v4(49.24,79.6) v4(49.24,78.6) v4(49.24,77.61) v4(49.24,76.61) v4(50.24,79.6) v4(50.24,78.6) v4(50.24,77.61) v4(50.24,76.61) v5(70.95,48.5) v5(70.95,47.17) v5(70.95,45.8) v5(70.95,44.43) v5(70.95,43.06) v5(72.33,48.5) v5(72.33,47.17) v5(72.33,45.8) v5(72.33,44.43) v5(72.33,43.06) v5(72.33,41.74) v5(73.7,48.5) v5(73.7,47.17) v5(73.7,45.8) v5(73.7,44.43) v5(73.7,43.06) v5(75.07,47.17) v5(75.07,45.8) v5(75.07,44.43) v5(75.07,43.06) v5(75.07,41.74)
